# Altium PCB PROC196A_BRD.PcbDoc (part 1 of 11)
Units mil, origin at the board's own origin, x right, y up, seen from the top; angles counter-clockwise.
Board outline 3346.45 x 4921.26 mil, 8 copper layers (Top Layer, GND1, SIG1, PWR1, PWR2, SIG2, GND2, Bottom Layer), stack 54.534 mil thick; 736 components, 498 nets, 3030 pads, 1279 vias.
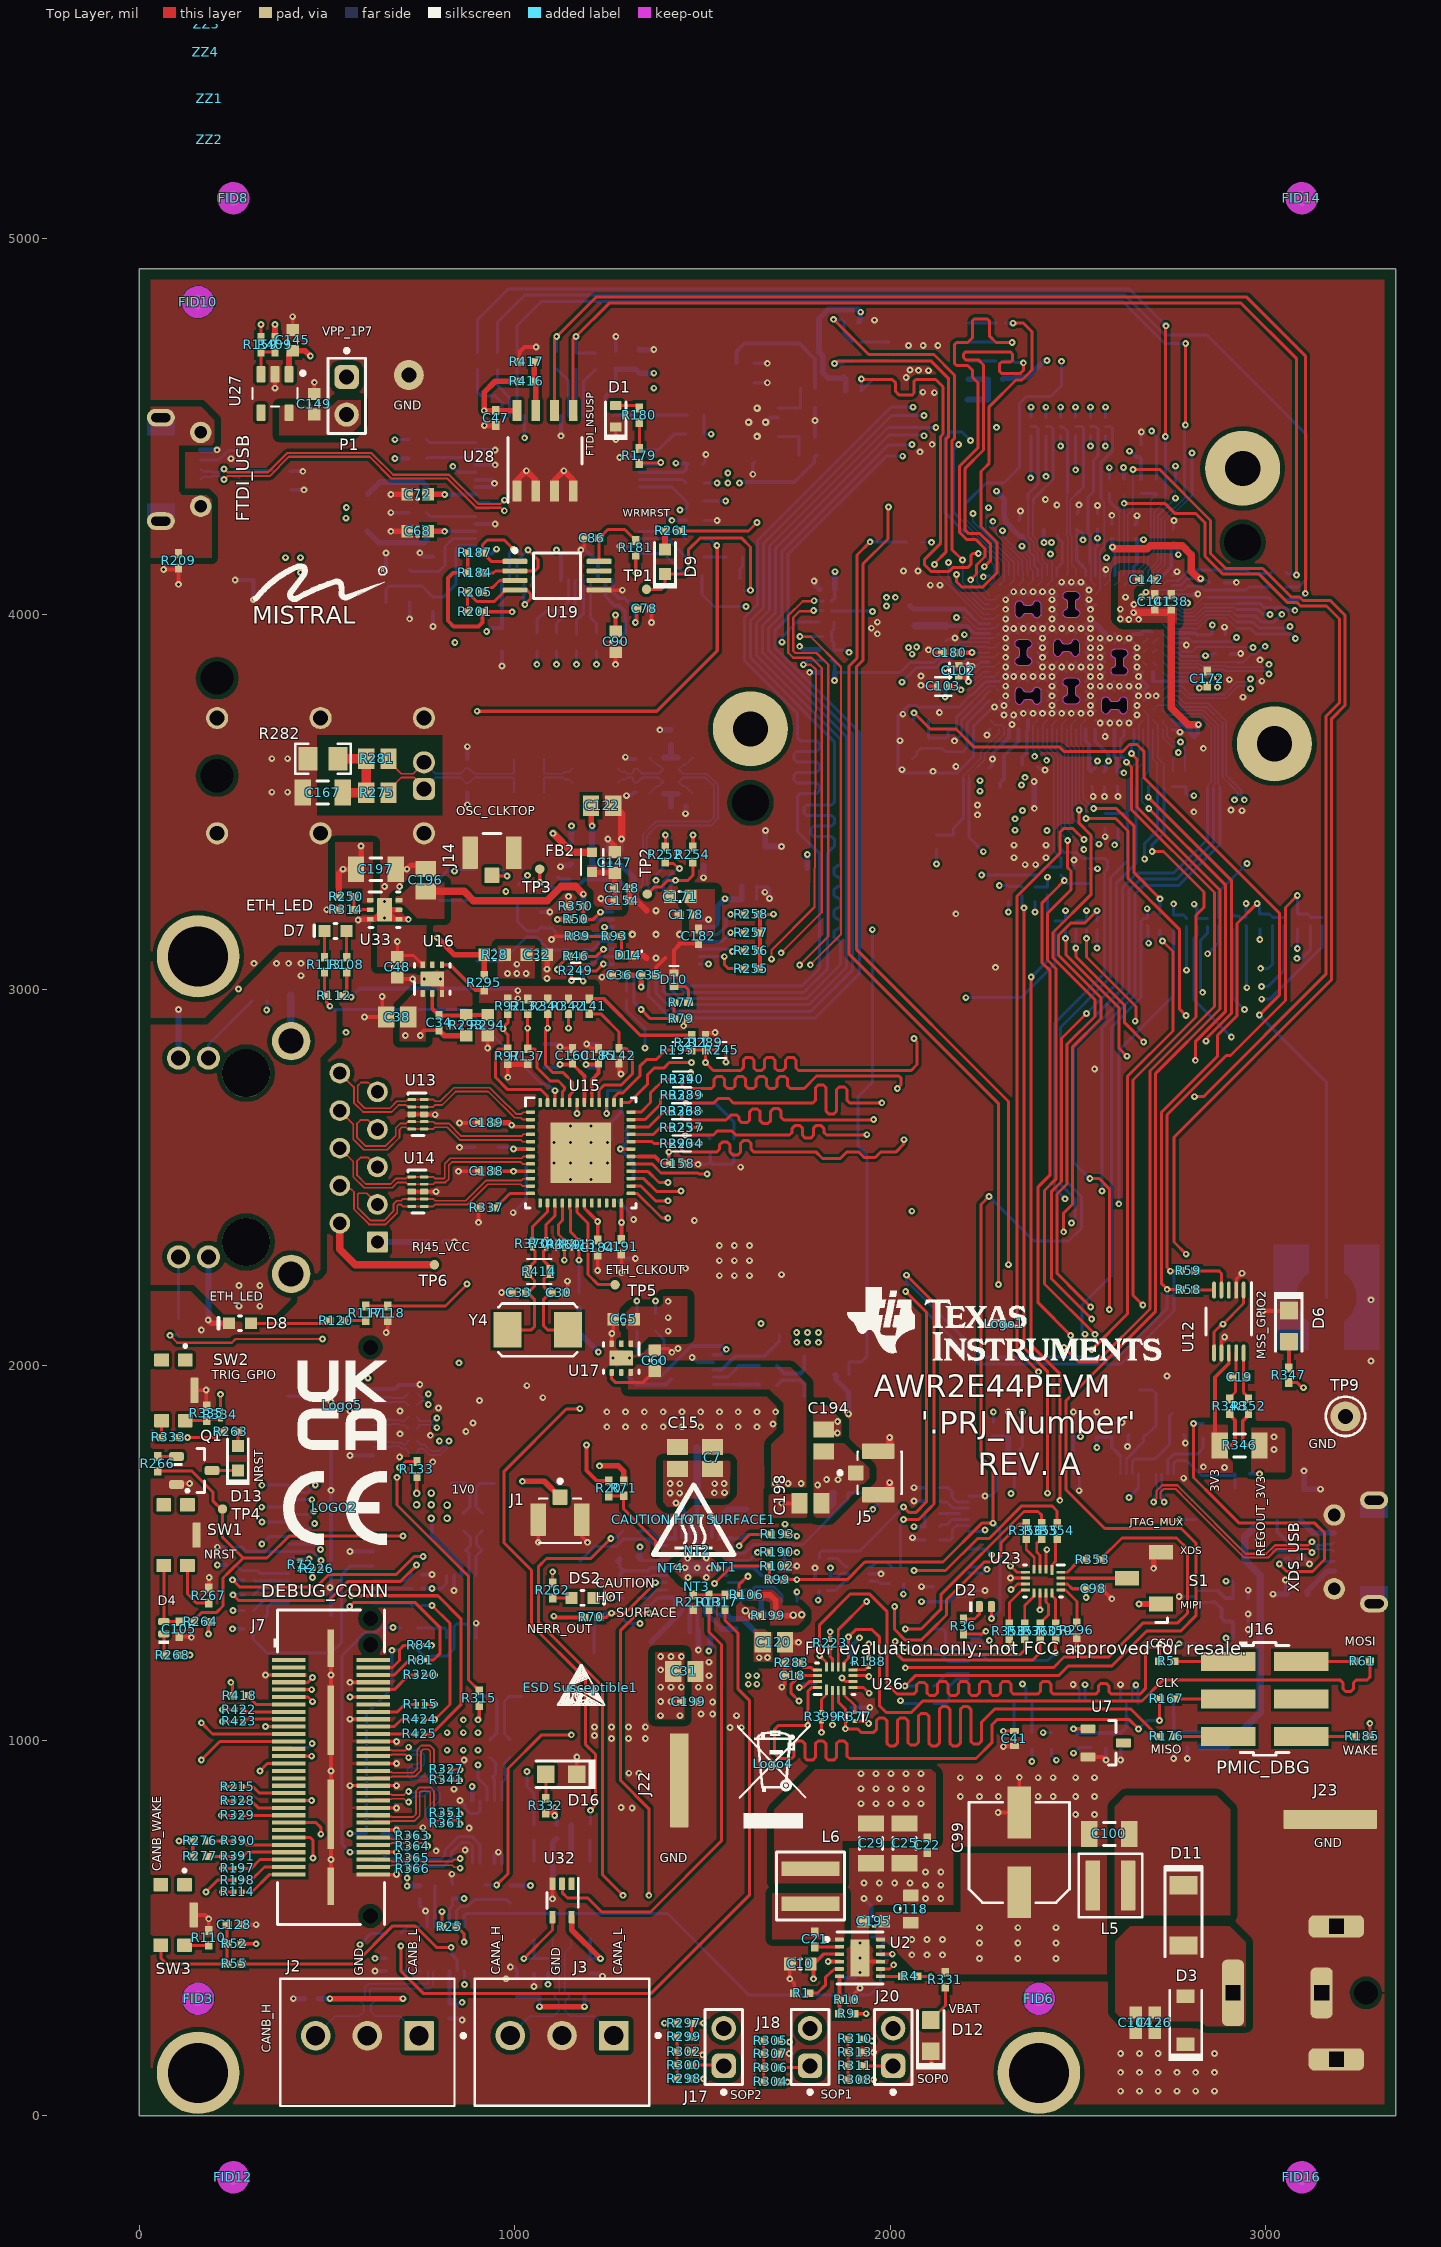
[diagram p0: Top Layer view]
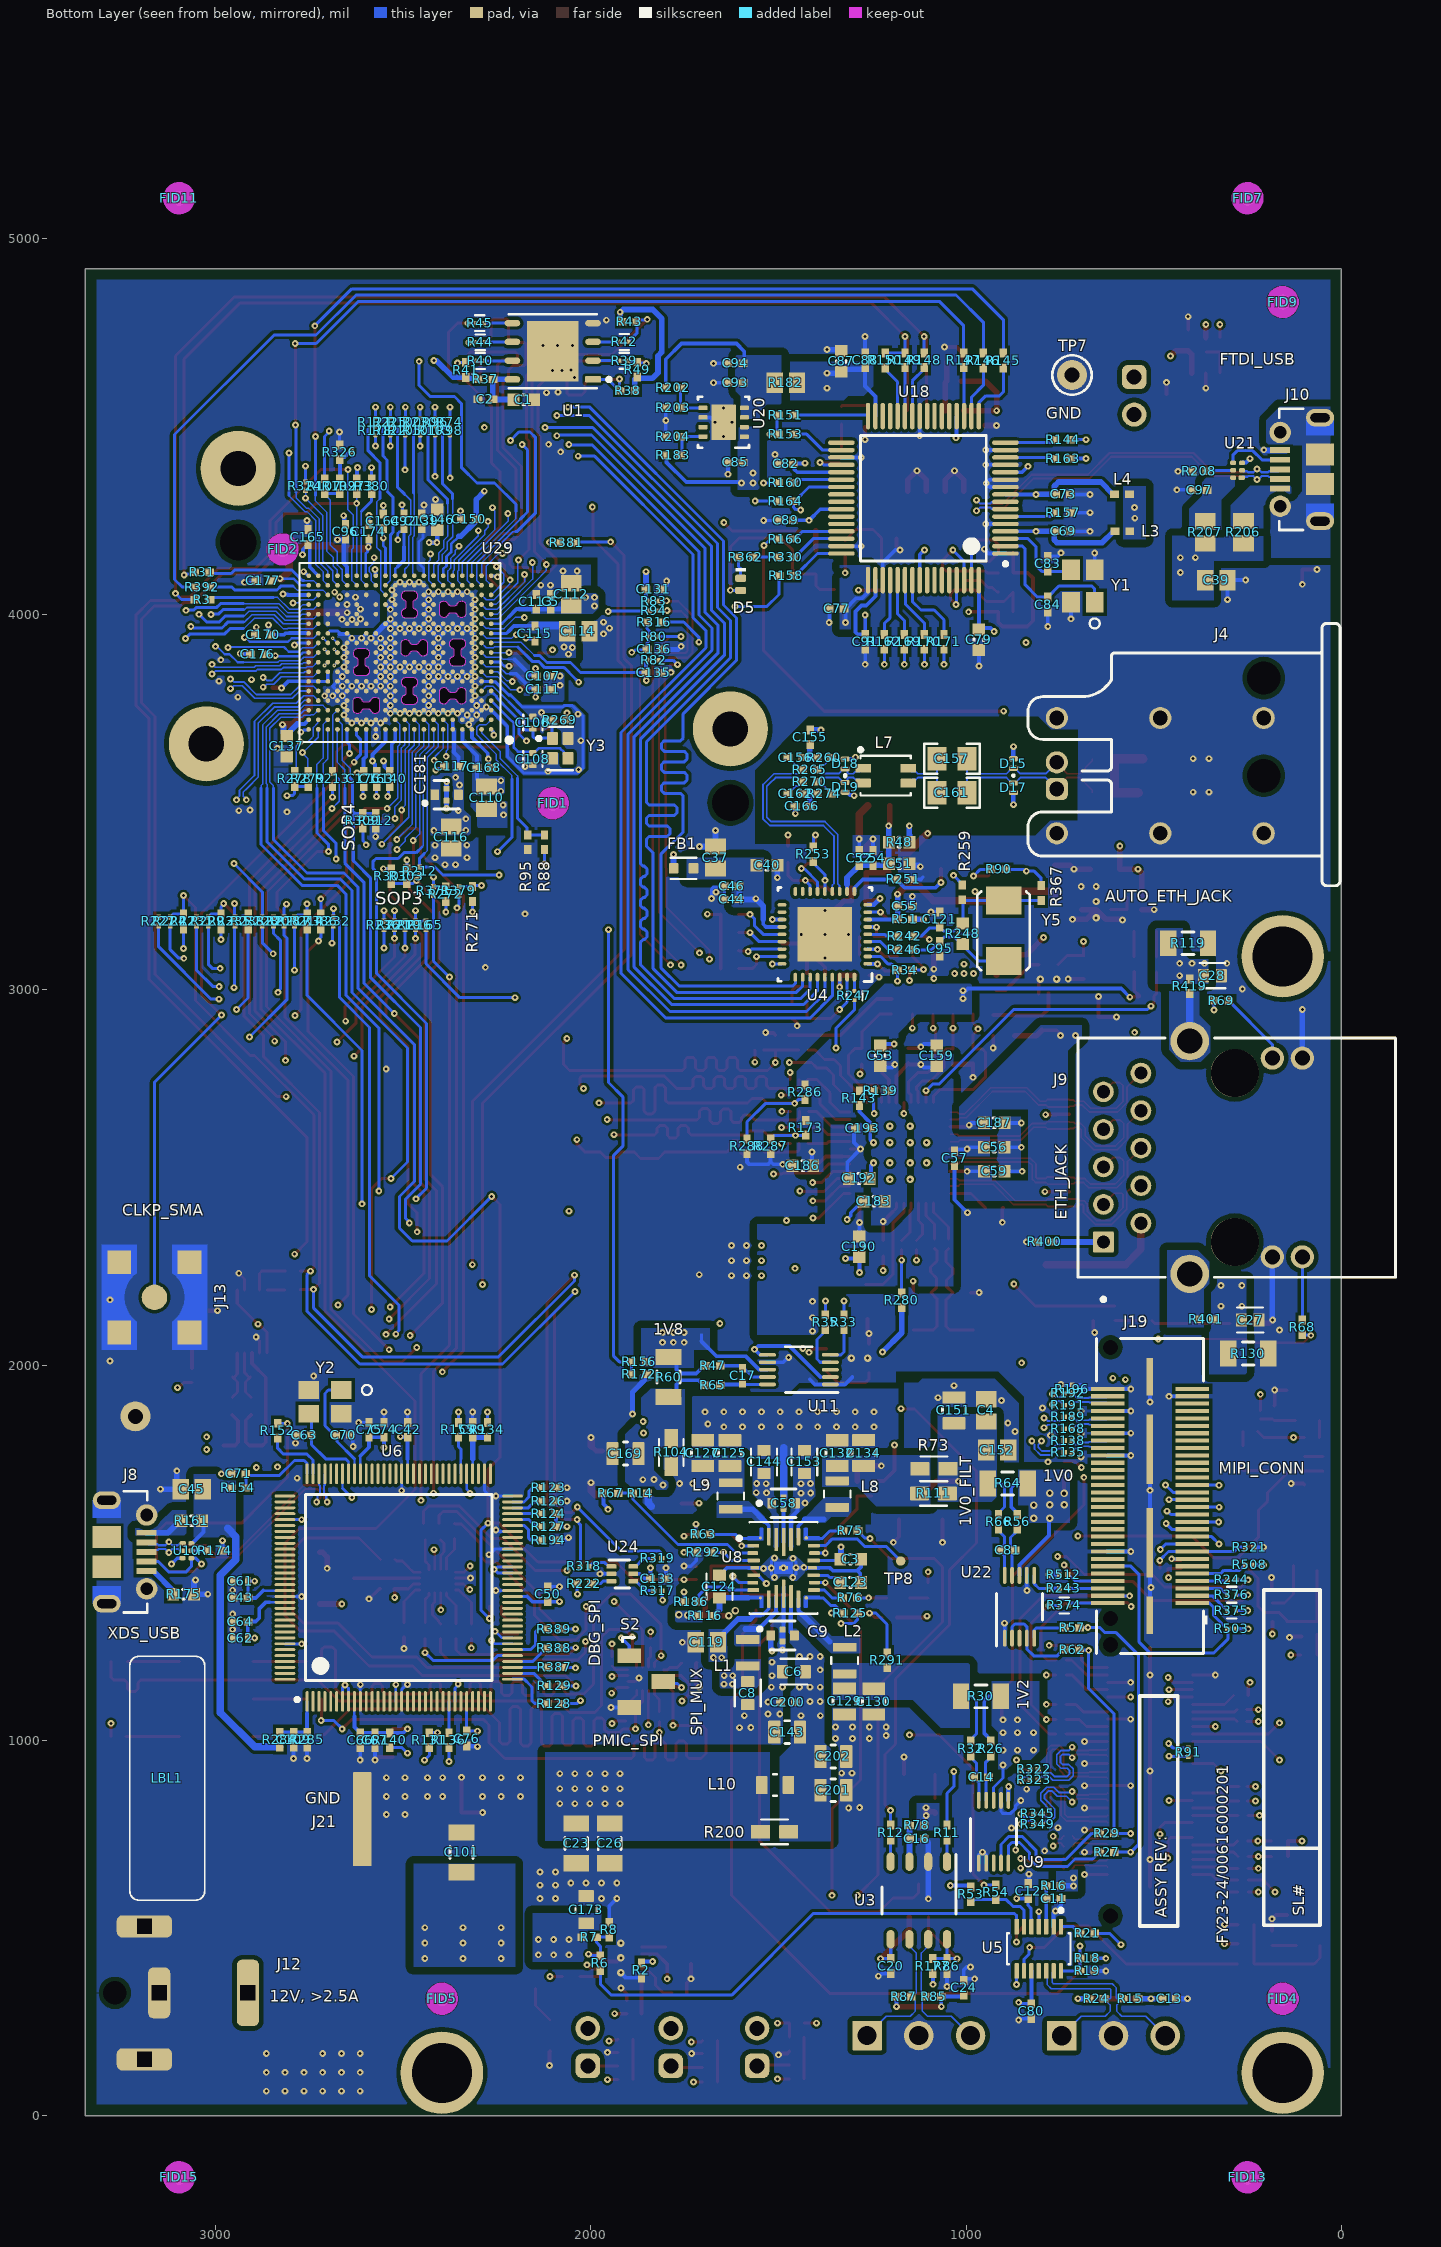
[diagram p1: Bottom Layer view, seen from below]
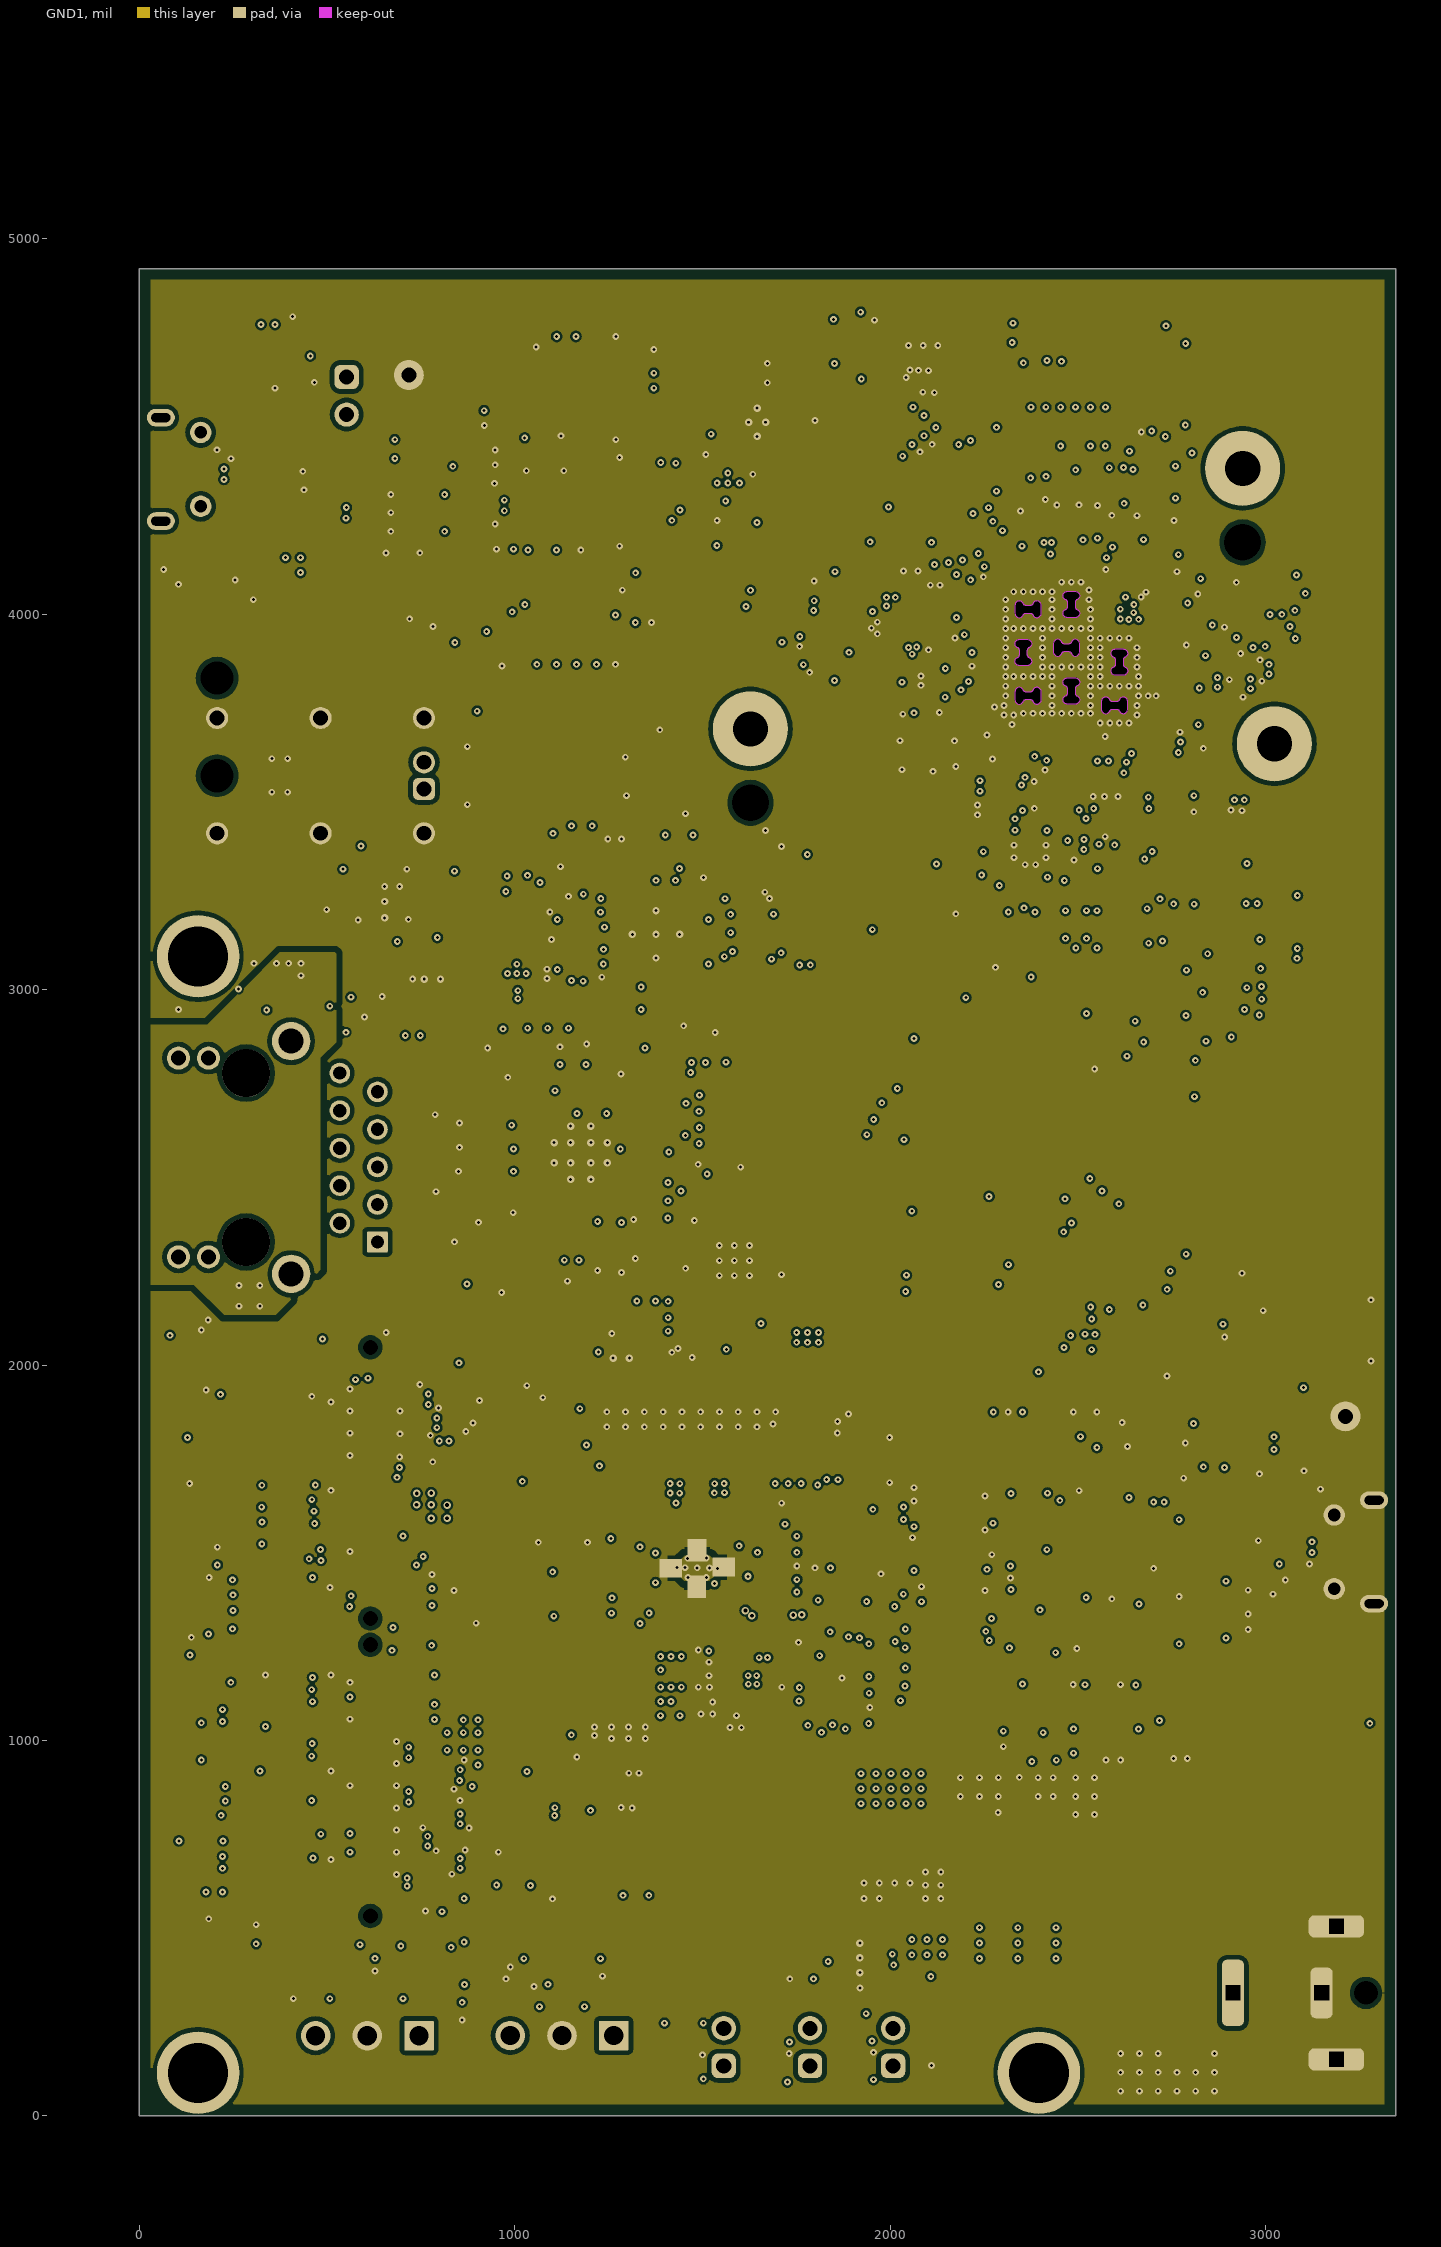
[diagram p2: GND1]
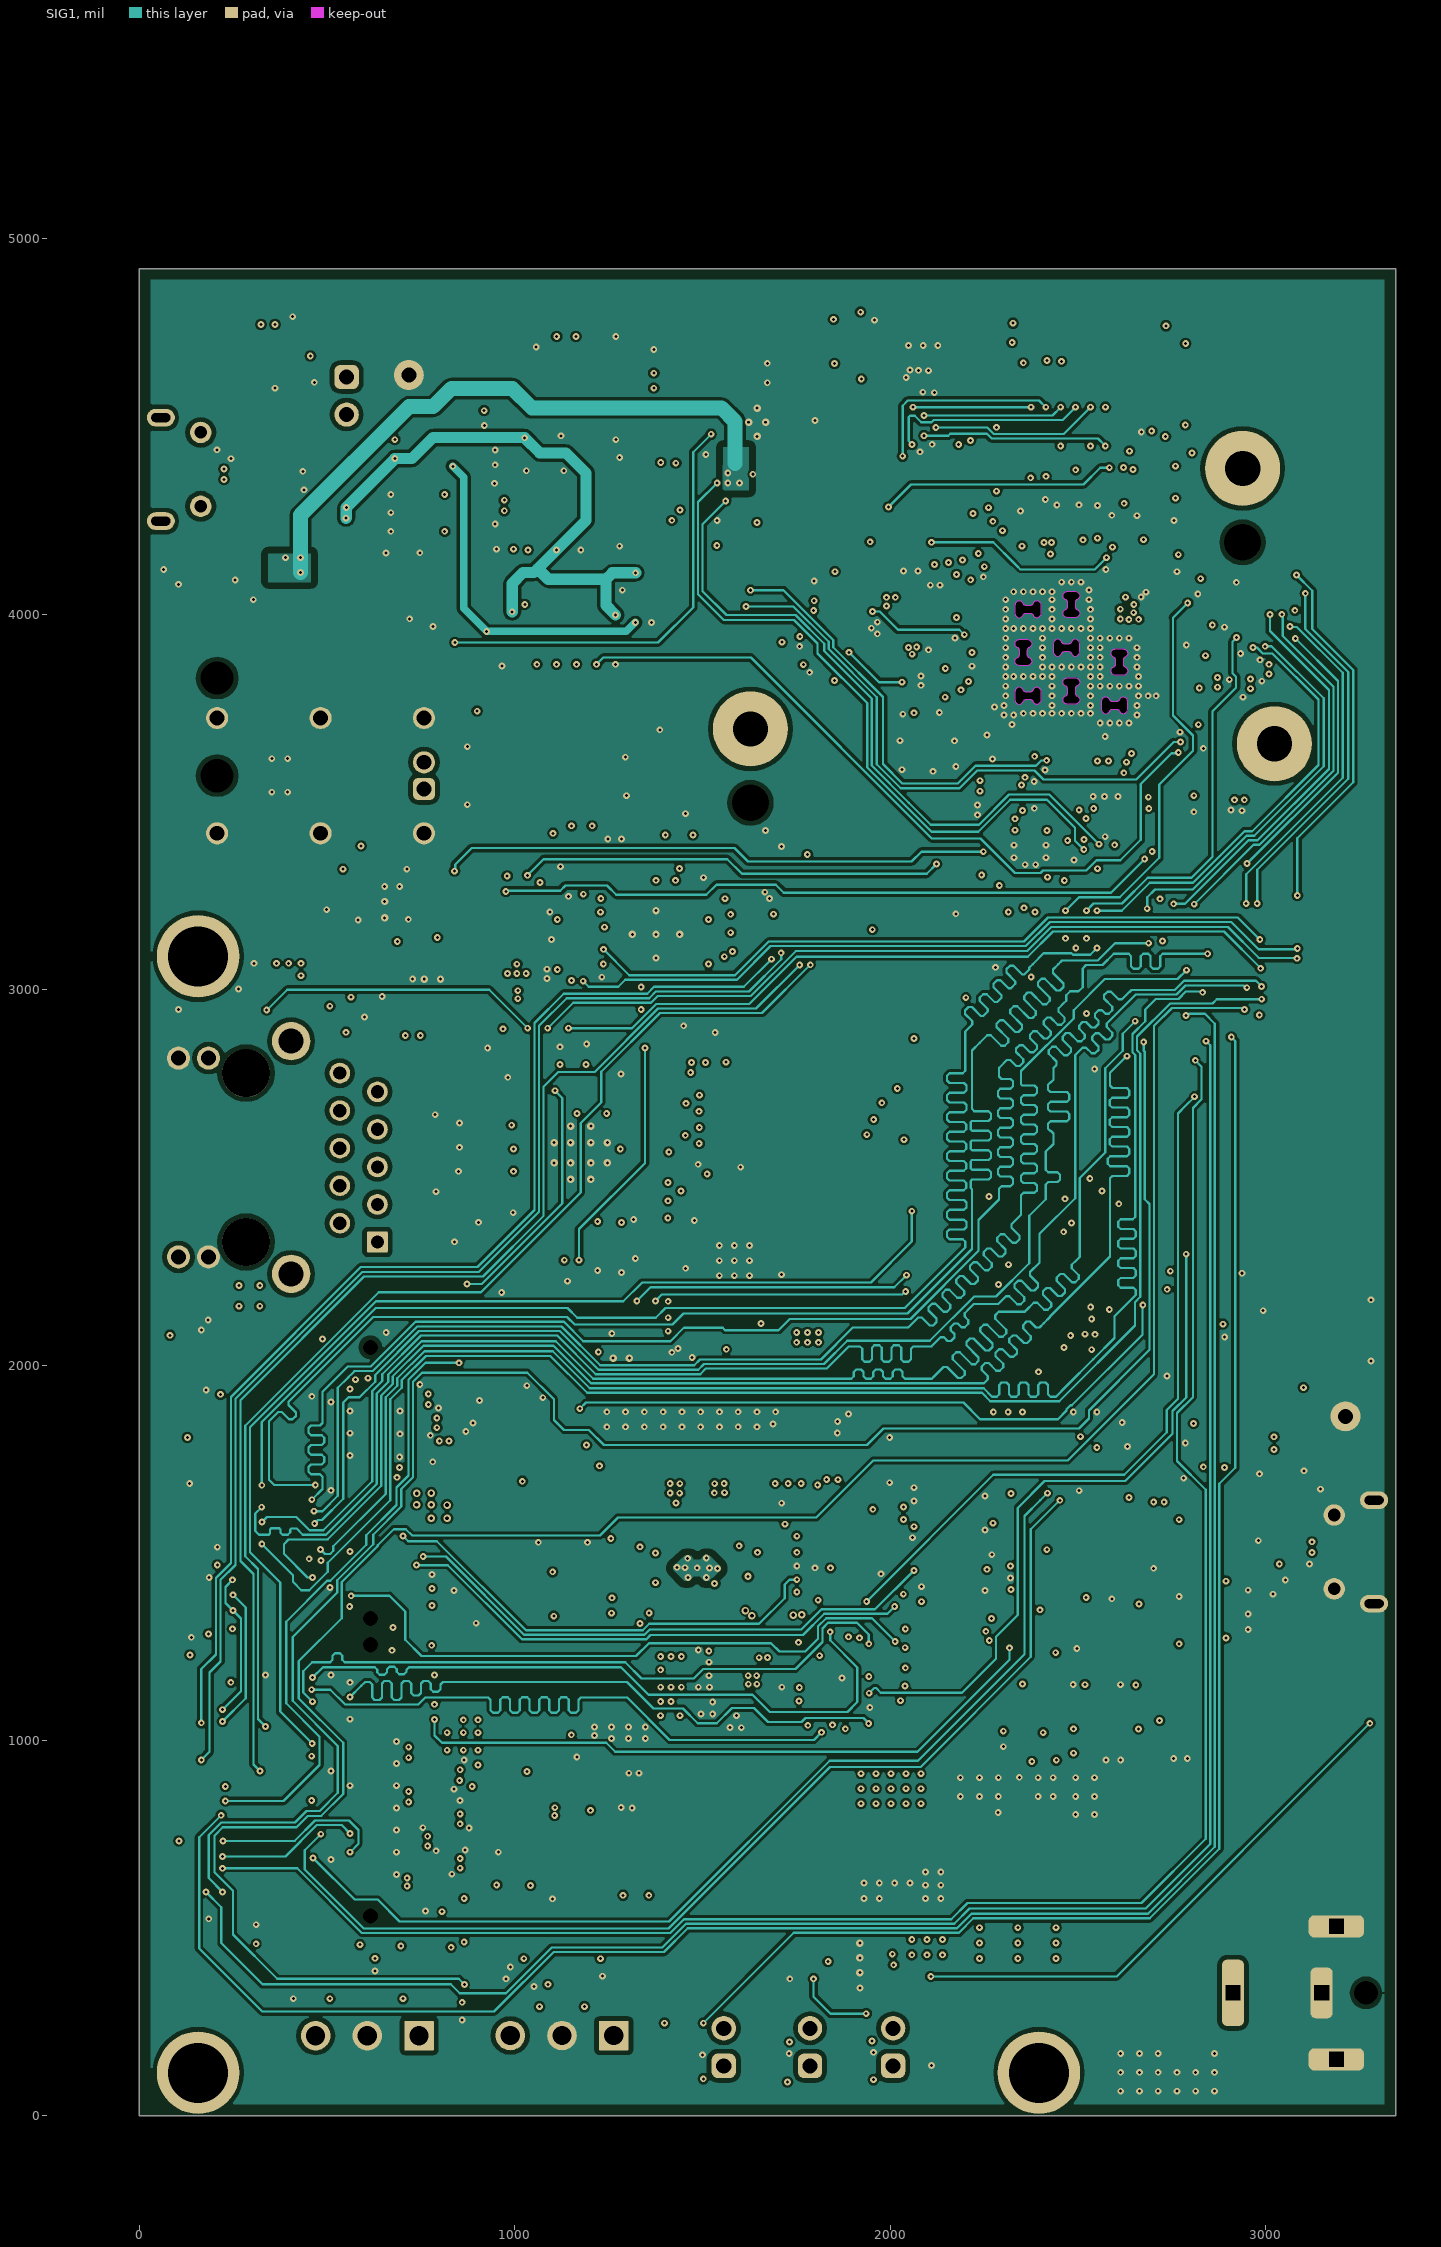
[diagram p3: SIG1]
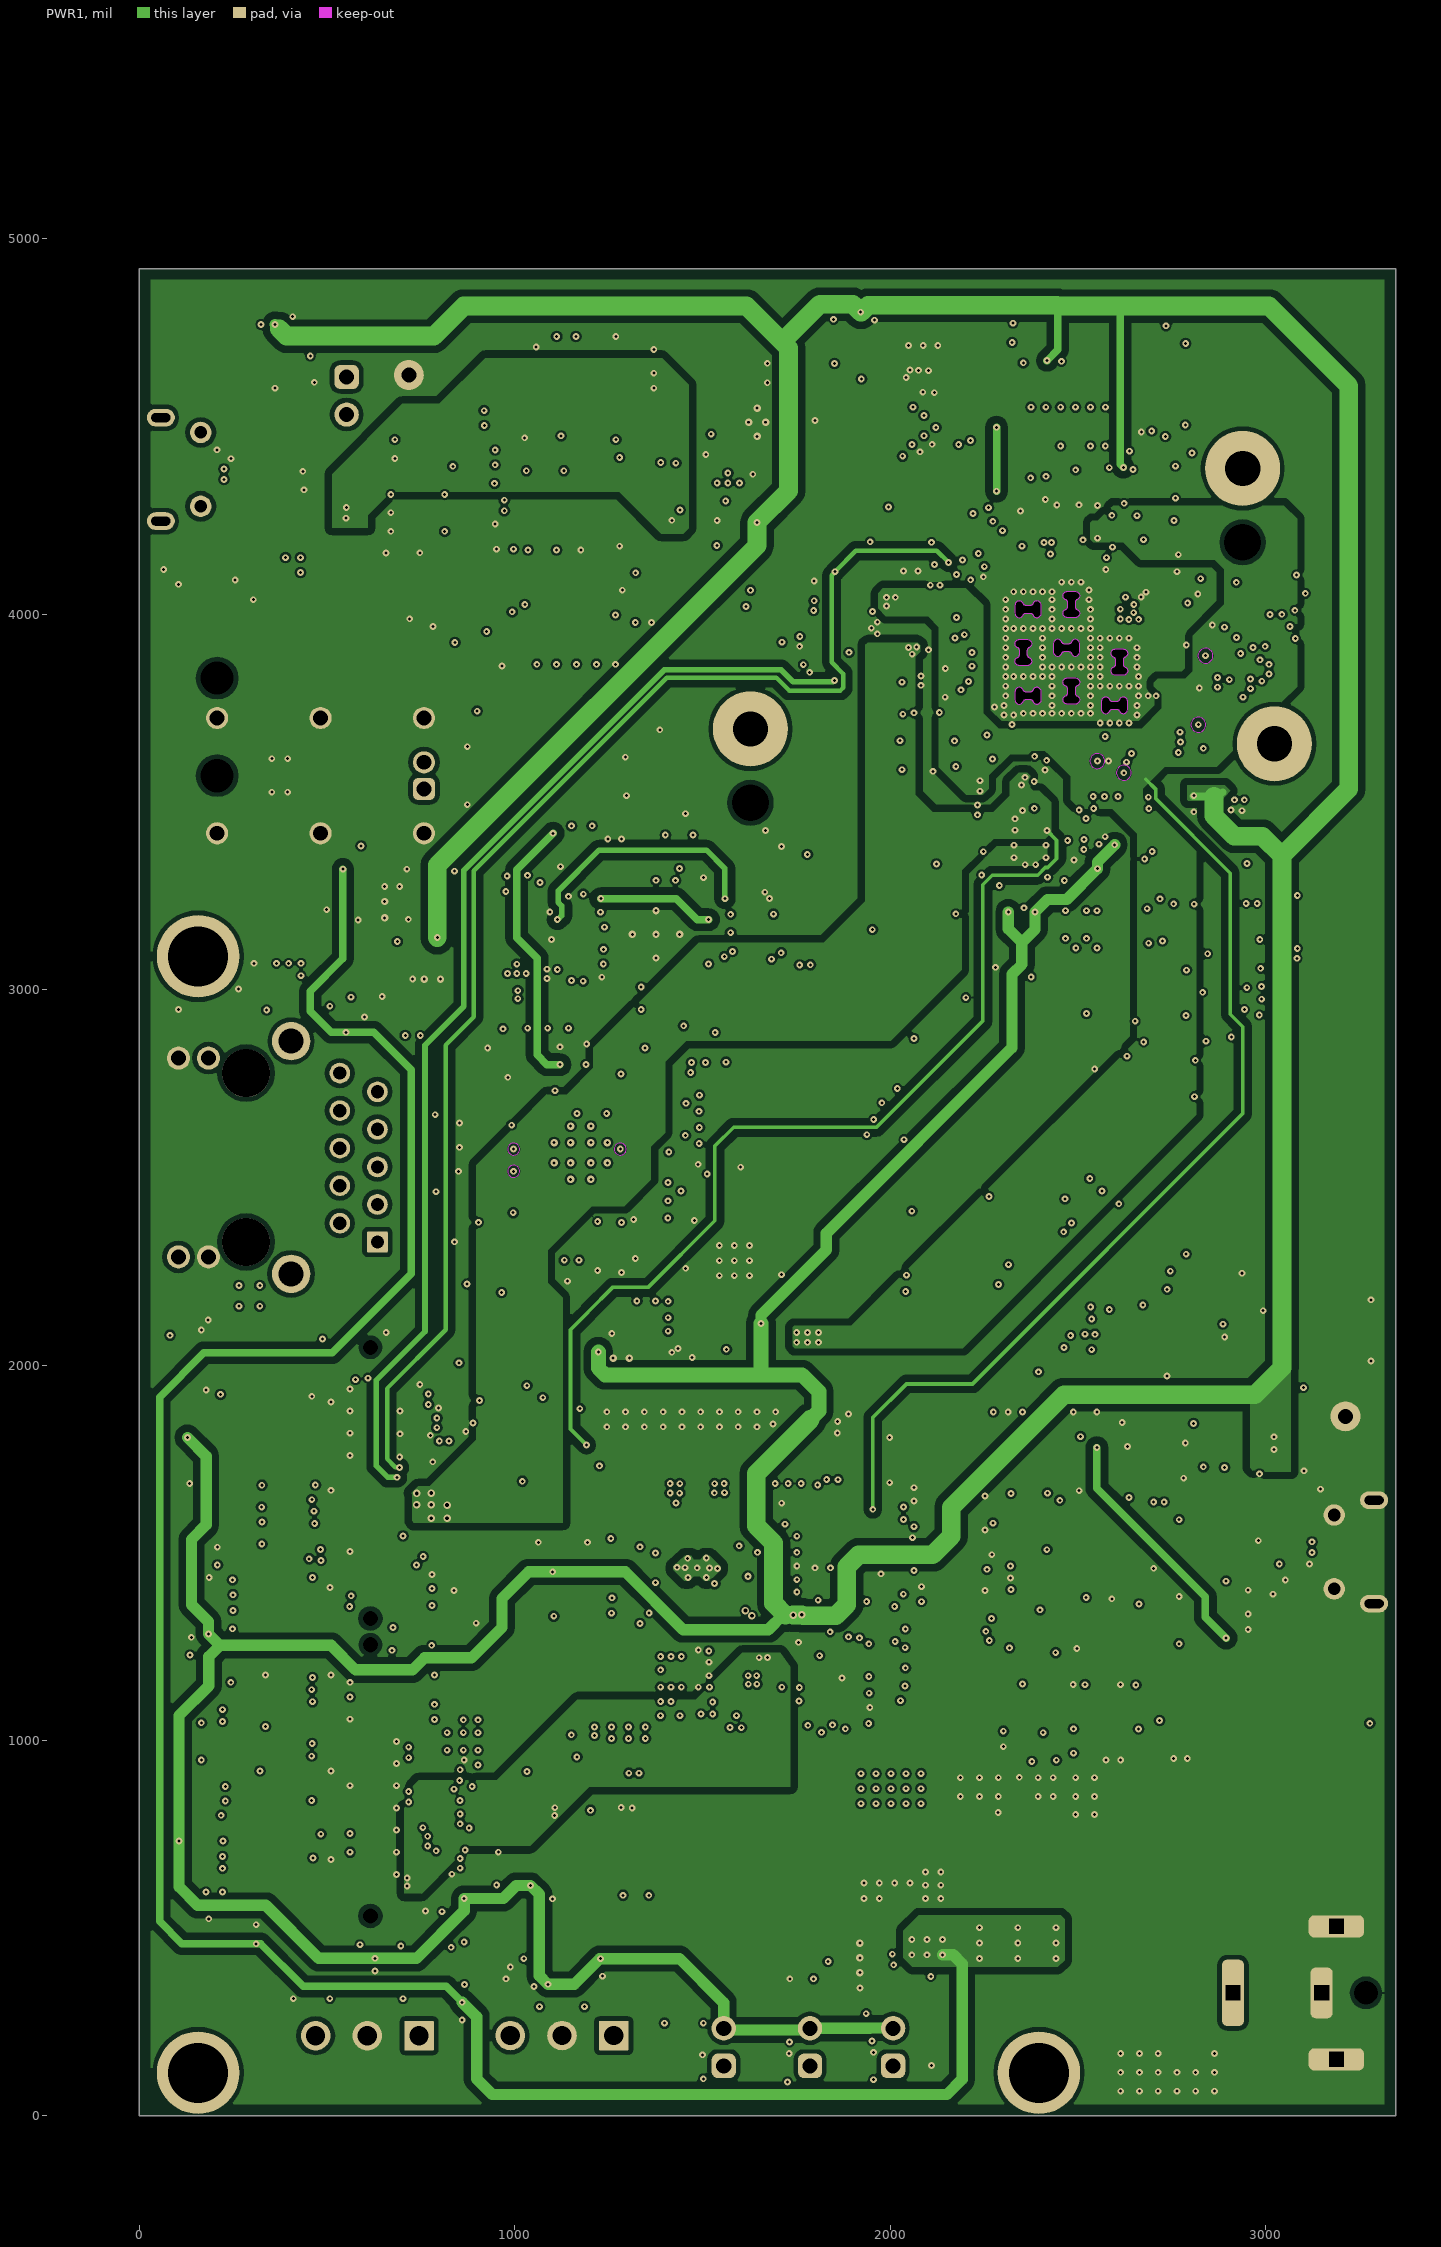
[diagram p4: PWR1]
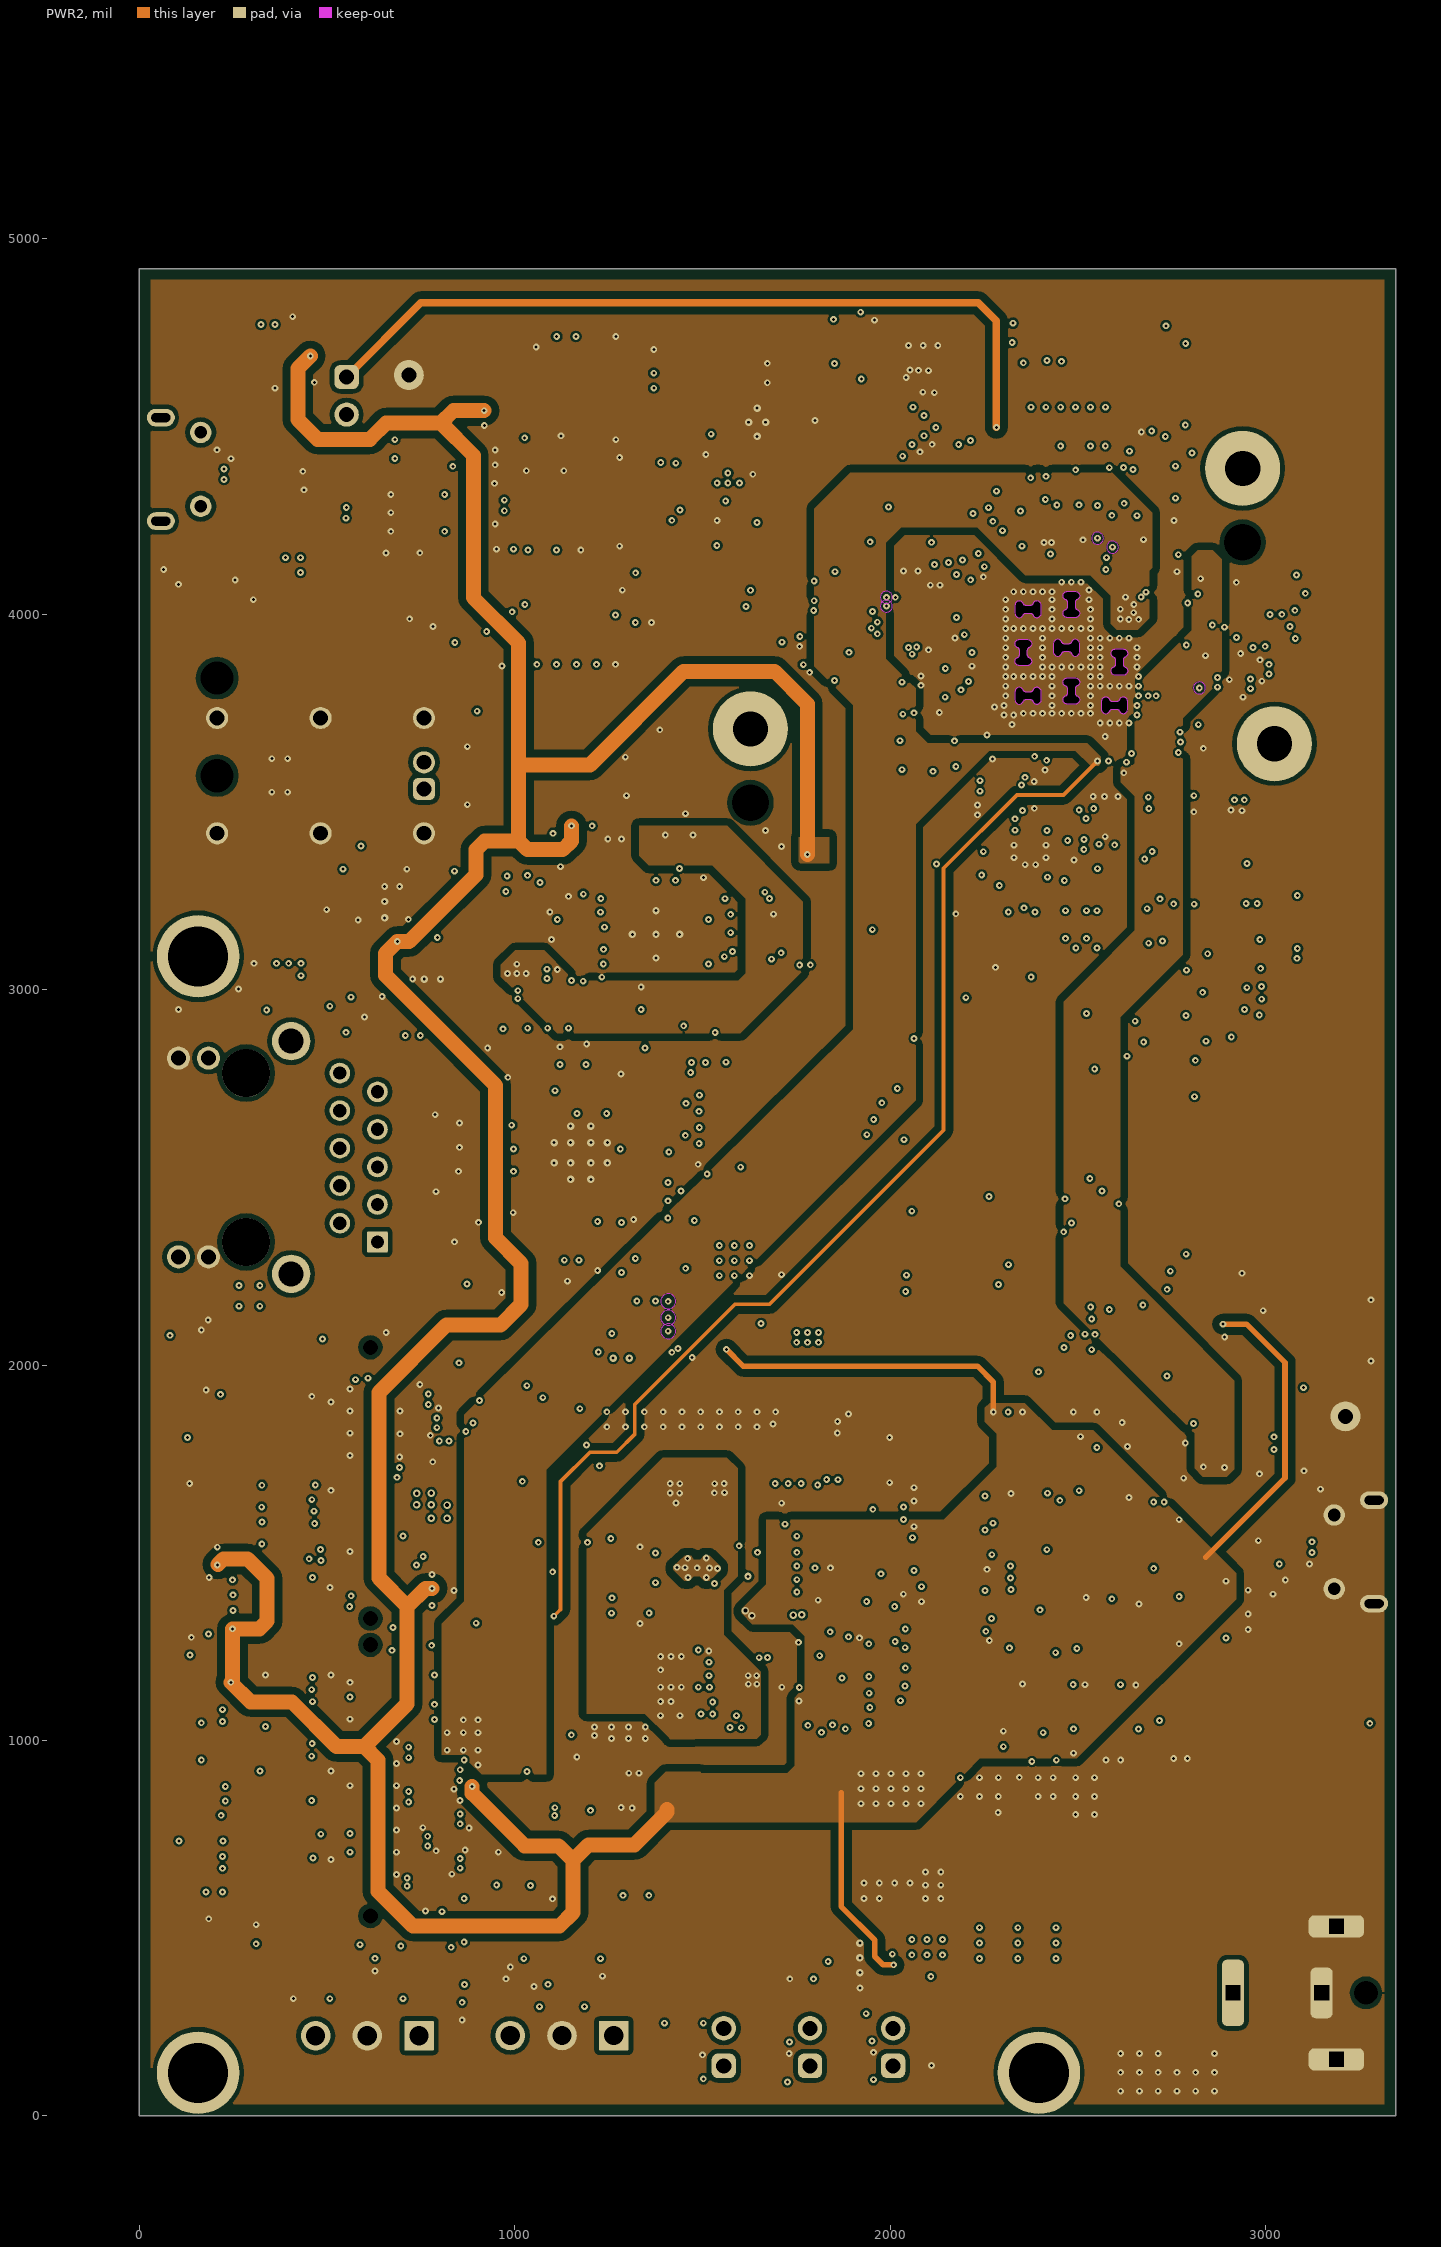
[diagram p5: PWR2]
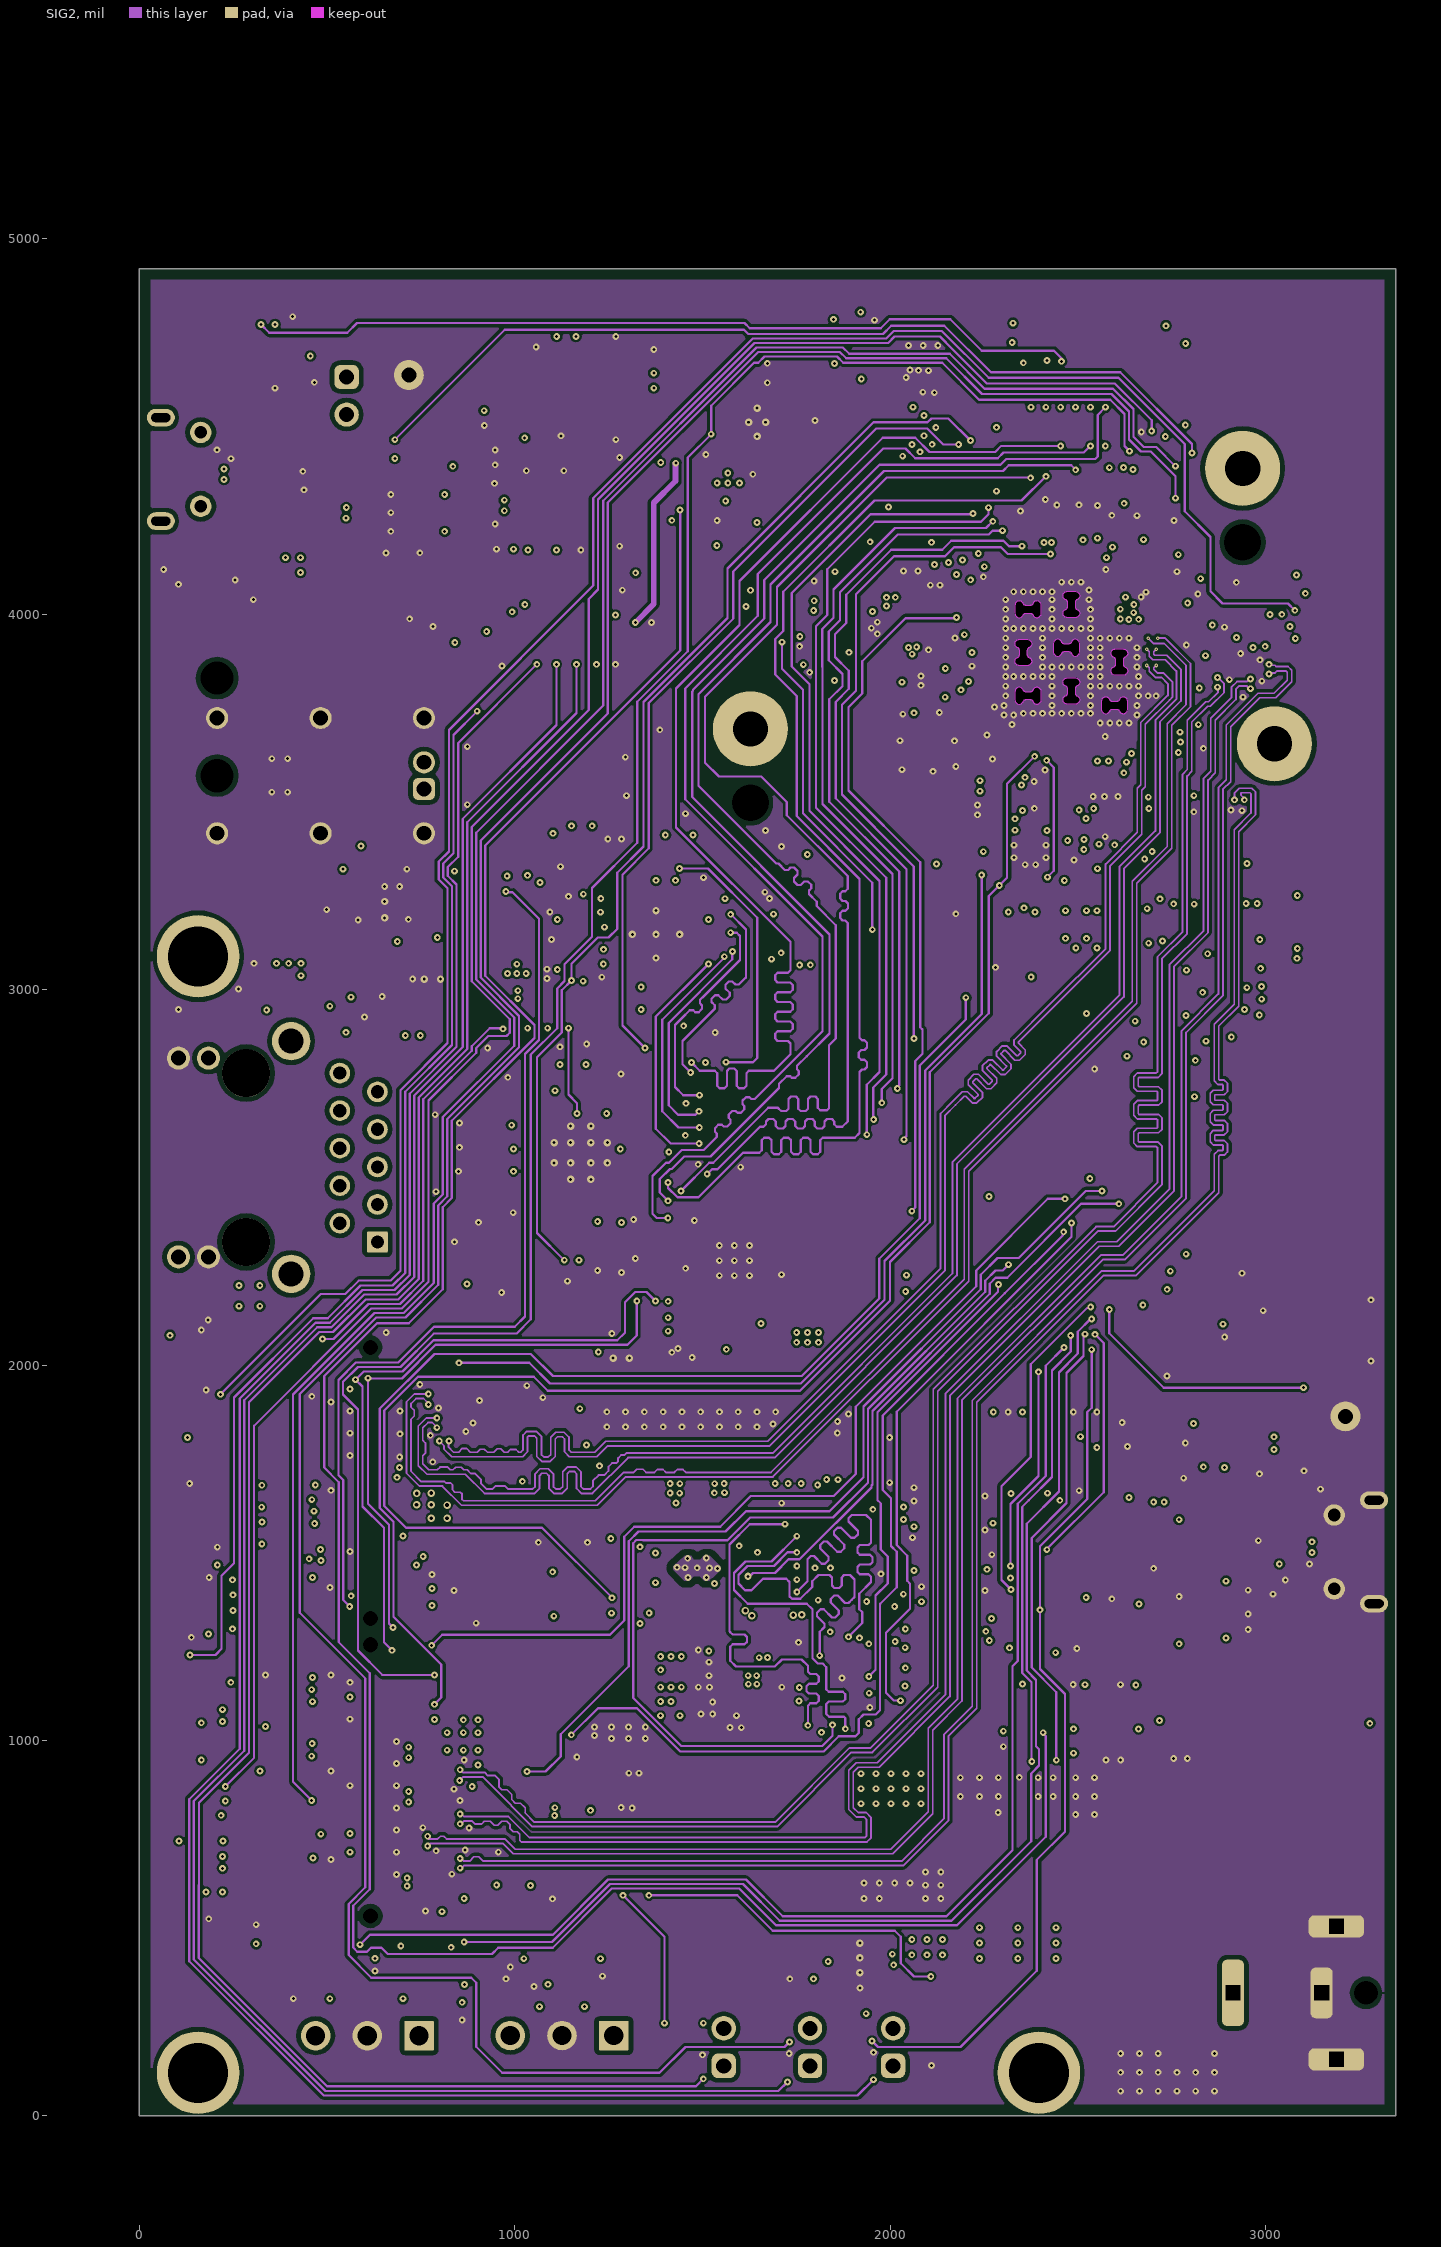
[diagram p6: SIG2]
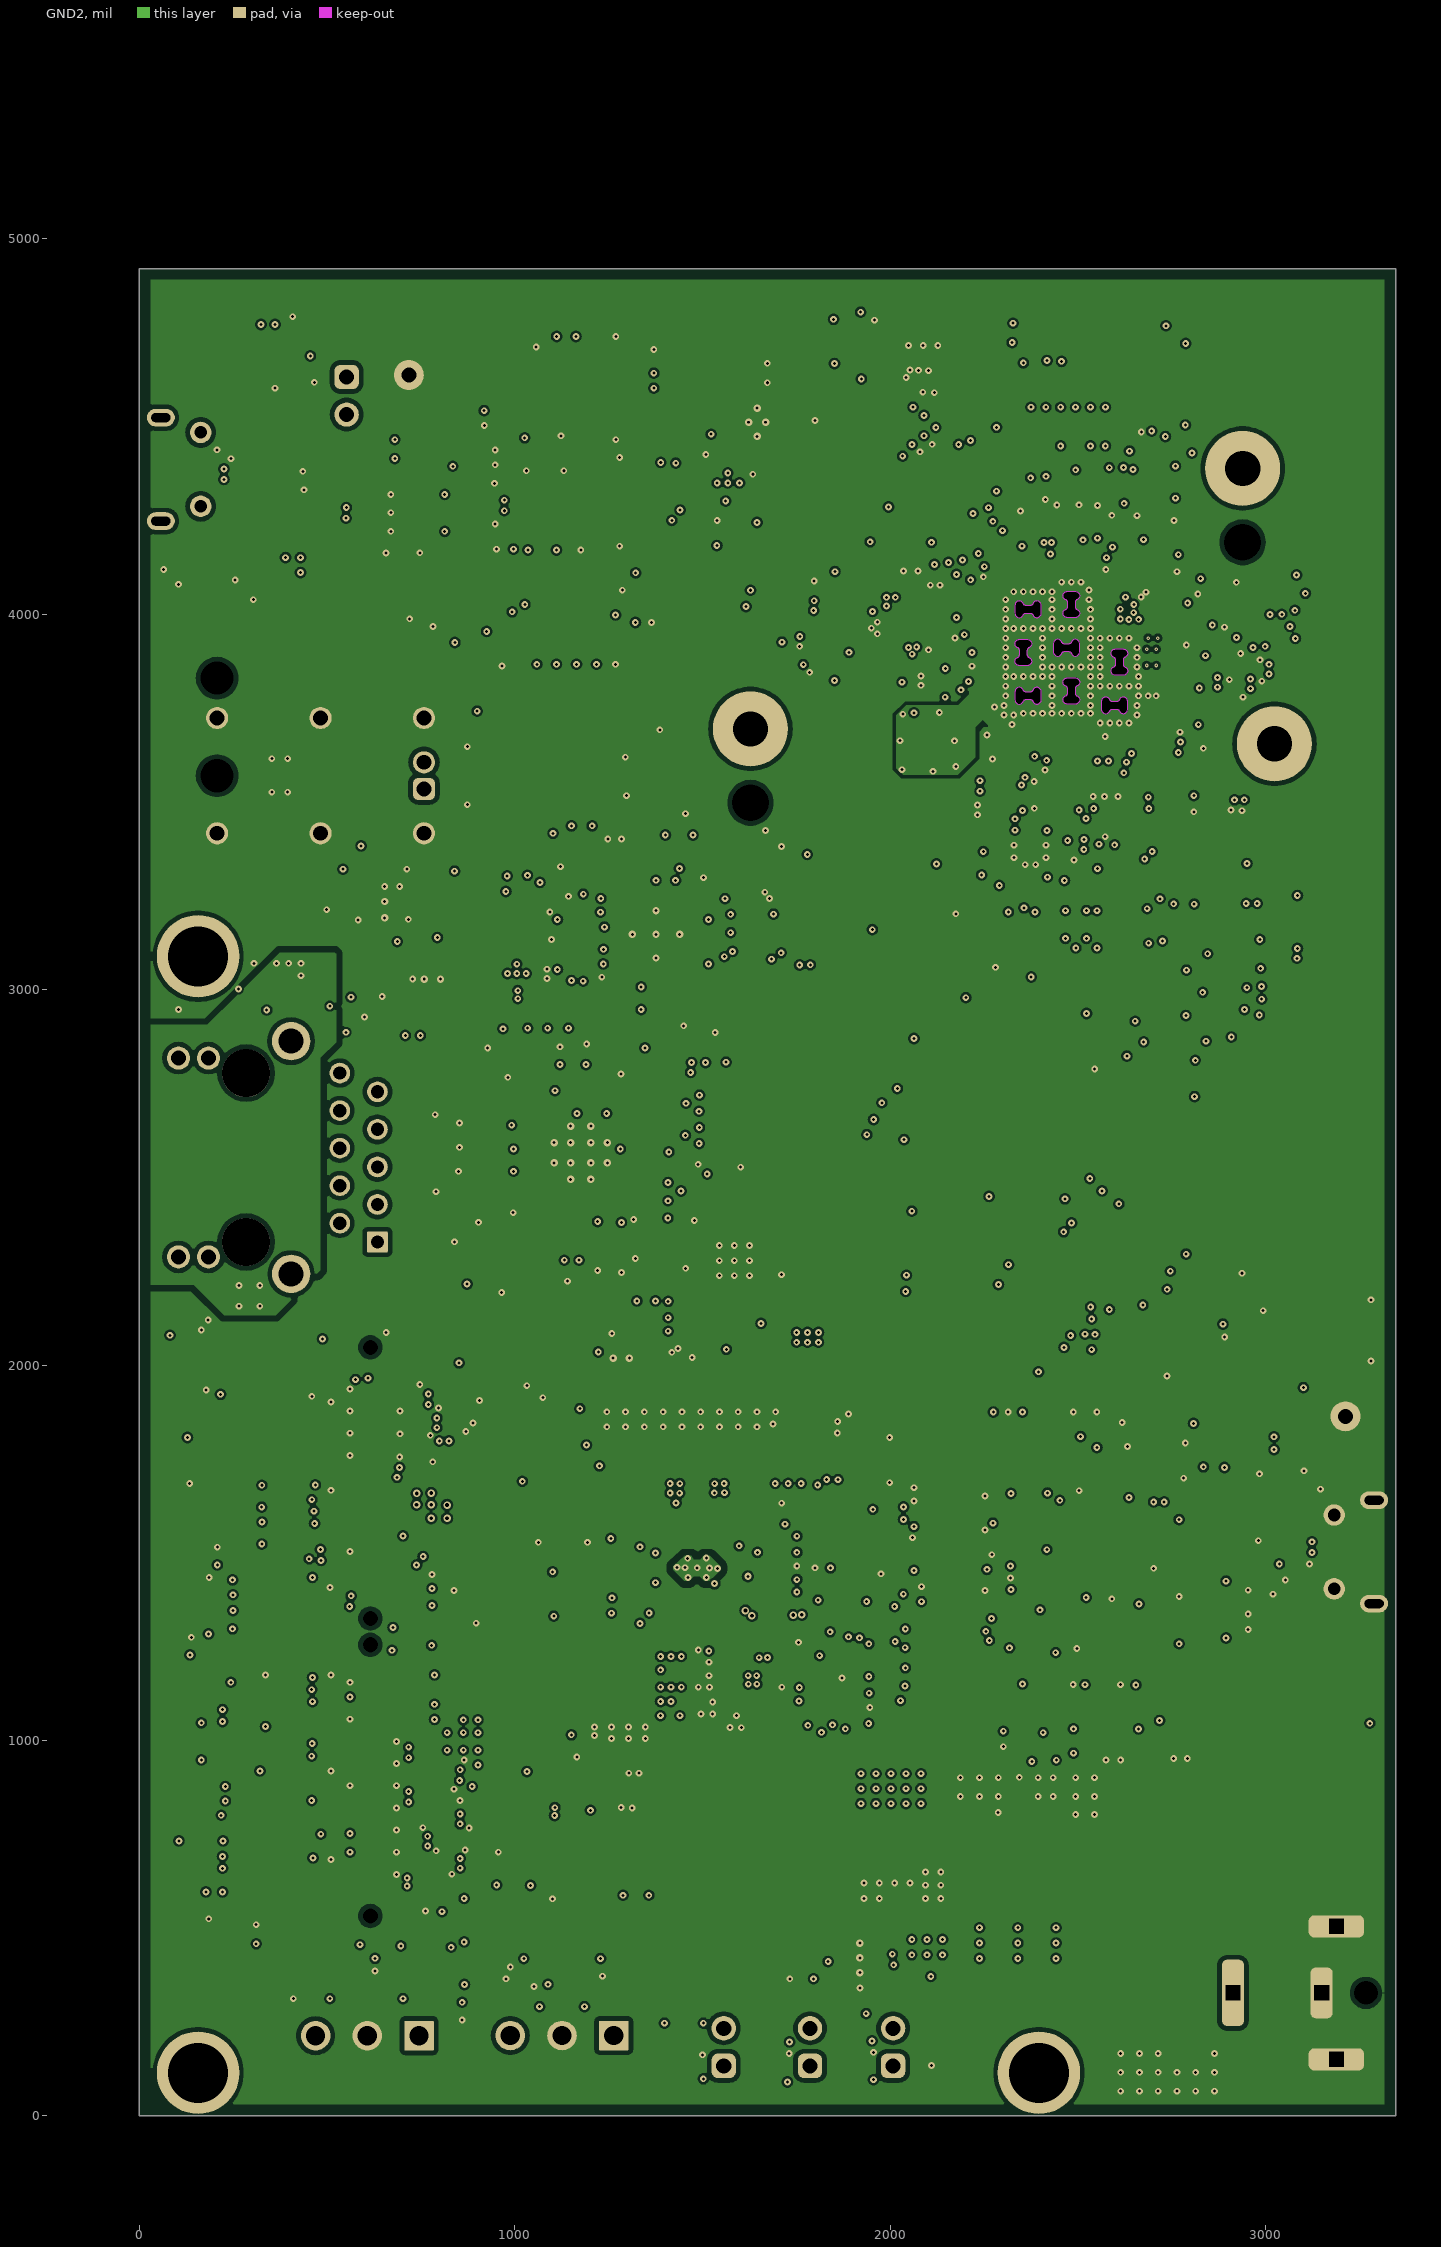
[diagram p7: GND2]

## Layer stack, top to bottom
Top Solder: solder mask 1, Solder Resist, Dk 3.5
Top Layer: signal copper 1.85
Dielectric 1: prepreg 4.396, FR-4 High Tg, Dk 3.54
GND1: signal copper 1.26
Dielectric 2: core 5, FR-4 High Tg, Dk 3.88
SIG1: signal copper 0.689
Dielectric 3: prepreg 10.312, FR-4 High Tg, Dk 3.86
PWR1: signal copper 1.26
Dielectric 4: prepreg 5, FR-4 High Tg, Dk 3.88
PWR2: signal copper 1.26
Dielectric 5: prepreg 10.312, FR-4 High Tg, Dk 3.86
SIG2: signal copper 0.689
Dielectric 6: core 5, FR-4 High Tg, Dk 3.88
GND2: signal copper 1.26
Dielectric 7: prepreg 4.396, FR-4 High Tg, Dk 3.54
Bottom Layer: signal copper 1.85
Bottom Solder: solder mask 1, Solder Resist, Dk 3.5

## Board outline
0,0 0,4921.25 3346.45,4921.26 3346.45,0
cut-out: 2336.08,3994.62 ccw(c2344.43,4002.97) 2344.24,3991.16 ccw(c2344.04,4002.97) 2352.39,3994.62 ccw(c2344.04,4002.97) 2355.01,3998.6 cw(c2362.33,3995.69) 2357.91,4002.21 cw(c2362.33,3995.69) 2362.33,4003.56 2373,4003.56 cw(c2373,3995.69) 2377.42,4002.21 cw(c2373,3995.69) 2380.31,3998.6 ccw(c2391.28,4002.97) 2382.93,3994.62 ccw(c2391.29,4002.97) 2391.09,3991.16 ccw(c2390.89,4002.97) 2399.24,3994.62 ccw(c2390.89,4002.97) 2402.7,4002.97 2402.7,4023.84 ccw(c2390.89,4023.84) 2399.24,4032.19 ccw(c2390.89,4023.84) 2391.09,4035.65 ccw(c2391.28,4023.84) 2382.93,4032.19 ccw(c2391.29,4023.84) 2380.31,4028.21 cw(c2373,4031.12) 2377.42,4024.6 cw(c2373,4031.12) 2373,4023.25 2362.33,4023.25 cw(c2362.33,4031.12) 2357.91,4024.6 cw(c2362.33,4031.12) 2355.01,4028.21 ccw(c2344.04,4023.84) 2352.39,4032.19 ccw(c2344.04,4023.84) 2344.24,4035.65 ccw(c2344.43,4023.84) 2336.08,4032.19 ccw(c2344.43,4023.84) 2332.62,4023.84 2332.62,4002.97 ccw(c2344.43,4002.97) 2332.64,4002.29 ccw(c2344.43,4002.97)
cut-out: 2336.08,3866.67 cw(c2344.43,3875.02) 2332.63,3874.82 cw(c2344.43,3874.63) 2336.08,3882.98 cw(c2344.43,3874.63) 2340.06,3885.6 ccw(c2337.15,3892.91) 2343.67,3888.49 ccw(c2337.15,3892.91) 2345.03,3892.91 2345.03,3903.58 ccw(c2337.15,3903.58) 2343.67,3908 ccw(c2337.15,3903.58) 2340.06,3910.9 cw(c2344.43,3921.87) 2336.08,3913.52 cw(c2344.43,3921.87) 2332.63,3921.67 cw(c2344.43,3921.48) 2336.08,3929.83 cw(c2344.43,3921.48) 2344.43,3933.29 2365.3,3933.29 cw(c2365.3,3921.48) 2373.65,3929.83 cw(c2365.3,3921.48) 2377.11,3921.67 cw(c2365.3,3921.87) 2373.65,3913.52 cw(c2365.3,3921.87) 2369.67,3910.9 ccw(c2372.58,3903.58) 2366.07,3908 ccw(c2372.58,3903.58) 2364.71,3903.58 2364.71,3892.91 ccw(c2372.58,3892.91) 2366.07,3888.49 ccw(c2372.58,3892.91) 2369.67,3885.6 cw(c2365.3,3874.63) 2373.65,3882.98 cw(c2365.3,3874.63) 2377.11,3874.82 cw(c2365.3,3875.02) 2373.65,3866.67 cw(c2365.3,3875.02) 2365.98,3863.23 cw(c2365.3,3875.02) 2365.3,3863.21 2344.43,3863.21 cw(c2344.43,3875.02)
cut-out: 2438.45,3892.26 ccw(c2446.8,3900.61) 2446.6,3888.8 ccw(c2446.4,3900.61) 2454.75,3892.26 ccw(c2446.4,3900.61) 2457.38,3896.24 cw(c2464.69,3893.33) 2460.27,3899.84 cw(c2464.69,3893.33) 2464.69,3901.2 2475.36,3901.2 cw(c2475.36,3893.33) 2479.78,3899.84 cw(c2475.36,3893.33) 2482.67,3896.24 ccw(c2493.65,3900.61) 2485.3,3892.26 ccw(c2493.65,3900.61) 2493.45,3888.8 ccw(c2493.25,3900.61) 2501.61,3892.26 ccw(c2493.25,3900.61) 2505.06,3900.61 2505.06,3921.48 ccw(c2493.25,3921.48) 2501.61,3929.83 ccw(c2493.25,3921.48) 2493.45,3933.28 ccw(c2493.65,3921.48) 2485.3,3929.83 ccw(c2493.65,3921.48) 2482.67,3925.85 cw(c2475.36,3928.76) 2479.78,3922.24 cw(c2475.36,3928.76) 2475.36,3920.89 2464.69,3920.89 cw(c2464.69,3928.76) 2460.27,3922.24 cw(c2464.69,3928.76) 2457.38,3925.85 ccw(c2446.41,3921.48) 2454.76,3929.83 ccw(c2446.4,3921.48) 2446.6,3933.28 ccw(c2446.8,3921.48) 2438.45,3929.83 ccw(c2446.8,3921.48) 2434.99,3921.48 2434.99,3900.61 ccw(c2446.8,3900.61) 2435.01,3899.93 ccw(c2446.8,3900.61)
cut-out: 2464.04,3994.62 cw(c2472.39,4002.97) 2460.58,4002.77 cw(c2472.39,4002.58) 2464.04,4010.93 cw(c2472.39,4002.58) 2468.02,4013.55 ccw(c2465.1,4020.87) 2471.62,4016.45 ccw(c2465.1,4020.87) 2472.98,4020.87 2472.98,4031.53 ccw(c2465.1,4031.53) 2471.62,4035.95 ccw(c2465.1,4031.54) 2468.02,4038.85 cw(c2472.39,4049.82) 2464.04,4041.47 cw(c2472.39,4049.82) 2460.58,4049.63 cw(c2472.39,4049.43) 2464.04,4057.78 cw(c2472.39,4049.43) 2472.39,4061.24 2493.25,4061.24 cw(c2493.25,4049.43) 2501.61,4057.78 cw(c2493.25,4049.43) 2505.06,4049.63 cw(c2493.25,4049.82) 2501.61,4041.47 cw(c2493.25,4049.82) 2497.62,4038.85 ccw(c2500.54,4031.53) 2494.02,4035.95 ccw(c2500.54,4031.53) 2492.66,4031.53 2492.66,4020.87 ccw(c2500.54,4020.87) 2494.02,4016.45 ccw(c2500.54,4020.87) 2497.62,4013.55 cw(c2493.26,4002.58) 2501.61,4010.93 cw(c2493.25,4002.58) 2505.06,4002.77 cw(c2493.25,4002.97) 2501.61,3994.62 cw(c2493.25,4002.97) 2493.94,3991.18 cw(c2493.25,4002.97) 2493.25,3991.16 2472.39,3991.16 cw(c2472.39,4002.97)
cut-out: 2591.99,3841.08 cw(c2600.34,3849.43) 2588.53,3849.23 cw(c2600.34,3849.03) 2591.99,3857.39 cw(c2600.34,3849.04) 2595.97,3860.01 ccw(c2593.06,3867.32) 2599.57,3862.9 ccw(c2593.06,3867.32) 2600.93,3867.32 2600.93,3877.99 ccw(c2593.06,3877.99) 2599.57,3882.41 ccw(c2593.06,3877.99) 2595.97,3885.31 cw(c2600.34,3896.28) 2591.99,3887.93 cw(c2600.34,3896.28) 2588.53,3896.08 cw(c2600.34,3895.89) 2591.99,3904.24 cw(c2600.34,3895.89) 2600.34,3907.7 2621.21,3907.7 cw(c2621.21,3895.89) 2629.56,3904.24 cw(c2621.21,3895.89) 2633.02,3896.08 cw(c2621.21,3896.28) 2629.56,3887.93 cw(c2621.21,3896.28) 2625.58,3885.31 ccw(c2628.49,3877.99) 2621.97,3882.41 ccw(c2628.49,3877.99) 2620.62,3877.99 2620.62,3867.32 ccw(c2628.49,3867.32) 2621.97,3862.9 ccw(c2628.49,3867.32) 2625.58,3860.01 cw(c2621.21,3849.04) 2629.56,3857.39 cw(c2621.21,3849.03) 2633.02,3849.23 cw(c2621.21,3849.43) 2629.56,3841.08 cw(c2621.21,3849.43) 2621.89,3837.64 cw(c2621.21,3849.43) 2621.21,3837.62 2600.34,3837.62 cw(c2600.34,3849.43)
cut-out: 2566.4,3738.71 ccw(c2574.75,3747.07) 2574.55,3735.26 ccw(c2574.36,3747.07) 2582.71,3738.71 ccw(c2574.36,3747.07) 2585.33,3742.7 cw(c2592.64,3739.78) 2588.22,3746.3 cw(c2592.64,3739.78) 2592.64,3747.66 2603.31,3747.66 cw(c2603.31,3739.78) 2607.73,3746.3 cw(c2603.31,3739.78) 2610.63,3742.7 ccw(c2621.6,3747.07) 2613.25,3738.71 ccw(c2621.6,3747.07) 2621.4,3735.26 ccw(c2621.21,3747.07) 2629.56,3738.71 ccw(c2621.21,3747.07) 2633.02,3747.07 2633.02,3767.93 ccw(c2621.21,3767.93) 2629.56,3776.28 ccw(c2621.21,3767.93) 2621.4,3779.74 ccw(c2621.6,3767.93) 2613.25,3776.28 ccw(c2621.6,3767.93) 2610.63,3772.3 cw(c2603.31,3775.22) 2607.73,3768.7 cw(c2603.31,3775.21) 2603.31,3767.34 2592.64,3767.34 cw(c2592.64,3775.22) 2588.22,3768.7 cw(c2592.64,3775.22) 2585.33,3772.3 ccw(c2574.36,3767.93) 2582.71,3776.28 ccw(c2574.36,3767.93) 2574.55,3779.74 ccw(c2574.75,3767.93) 2566.4,3776.28 ccw(c2574.75,3767.93) 2562.94,3767.93 2562.94,3747.07 ccw(c2574.75,3747.07) 2562.96,3746.38 ccw(c2574.75,3747.07)
cut-out: 2464.04,3764.3 cw(c2472.39,3772.66) 2460.58,3772.46 cw(c2472.39,3772.26) 2464.04,3780.61 cw(c2472.39,3772.26) 2468.02,3783.24 ccw(c2465.1,3790.55) 2471.62,3786.13 ccw(c2465.1,3790.55) 2472.98,3790.55 2472.98,3801.22 ccw(c2465.1,3801.22) 2471.62,3805.64 ccw(c2465.1,3801.22) 2468.02,3808.53 cw(c2472.39,3819.51) 2464.04,3811.16 cw(c2472.39,3819.51) 2460.58,3819.31 cw(c2472.39,3819.11) 2464.04,3827.47 cw(c2472.39,3819.11) 2472.39,3830.92 2493.25,3830.92 cw(c2493.25,3819.11) 2501.61,3827.47 cw(c2493.25,3819.11) 2505.06,3819.31 cw(c2493.25,3819.51) 2501.61,3811.16 cw(c2493.25,3819.51) 2497.62,3808.53 ccw(c2500.54,3801.22) 2494.02,3805.64 ccw(c2500.54,3801.22) 2492.66,3801.22 2492.66,3790.55 ccw(c2500.54,3790.55) 2494.02,3786.13 ccw(c2500.54,3790.55) 2497.62,3783.24 cw(c2493.26,3772.26) 2501.61,3780.61 cw(c2493.25,3772.26) 2505.06,3772.46 cw(c2493.25,3772.66) 2501.61,3764.3 cw(c2493.25,3772.66) 2493.94,3760.87 cw(c2493.25,3772.66) 2493.25,3760.85 2472.39,3760.85 cw(c2472.39,3772.66)
cut-out: 2336.08,3764.31 ccw(c2344.43,3772.66) 2344.24,3760.85 ccw(c2344.04,3772.66) 2352.39,3764.31 ccw(c2344.04,3772.66) 2355.01,3768.29 cw(c2362.33,3765.37) 2357.91,3771.89 cw(c2362.33,3765.37) 2362.33,3773.25 2373,3773.25 cw(c2373,3765.37) 2377.42,3771.89 cw(c2373,3765.37) 2380.31,3768.29 ccw(c2391.28,3772.66) 2382.93,3764.31 ccw(c2391.29,3772.66) 2391.09,3760.85 ccw(c2390.89,3772.66) 2399.24,3764.31 ccw(c2390.89,3772.66) 2402.7,3772.66 2402.7,3793.52 ccw(c2390.89,3793.52) 2399.24,3801.87 ccw(c2390.89,3793.52) 2391.09,3805.33 ccw(c2391.28,3793.52) 2382.93,3801.87 ccw(c2391.29,3793.52) 2380.31,3797.89 cw(c2373,3800.81) 2377.42,3794.29 cw(c2373,3800.81) 2373,3792.93 2362.33,3792.93 cw(c2362.33,3800.81) 2357.91,3794.29 cw(c2362.33,3800.81) 2355.01,3797.89 ccw(c2344.04,3793.52) 2352.39,3801.87 ccw(c2344.04,3793.52) 2344.24,3805.33 ccw(c2344.43,3793.52) 2336.08,3801.87 ccw(c2344.43,3793.52) 2332.62,3793.52 2332.62,3772.66 ccw(c2344.43,3772.66) 2332.64,3771.97 ccw(c2344.43,3772.66)

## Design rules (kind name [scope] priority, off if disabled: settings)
AcuteAngle [All] p1: minimum=4.50000000000000E+0001 checktracksonly=TRUE
AssemblyTestPointUsage [All] p1: valid=2
BoardOutlineClearance USB_CONN [InComponent('J8')or InComponent('J10')] p1: gap=80 ignorepadtopadclearanceinfootprint=FALSE except(0: THPad-OutlineEdge Text-OutlineEdge Text-CavityEdge Text-CutoutEdge Text-SplitBarrior Text-SplitContinuation; 16: Track-CutoutEdge; 19: SMDPad-OutlineEdge Fill-OutlineEdge; 30: Arc-OutlineEdge Track-OutlineEdge Via-OutlineEdge Poly-OutlineEdge Region-OutlineEdge)
BoardOutlineClearance DogBone [WithinRoom('BGA')] p2: gap=7 ignorepadtopadclearanceinfootprint=FALSE except(0: Arc-SplitContinuation Track-SplitContinuation SMDPad-SplitContinuation THPad-SplitContinuation Via-SplitContinuation Fill-SplitContinuation Poly-OutlineEdge Poly-CavityEdge Poly-CutoutEdge Poly-SplitBarrior Poly-SplitContinuation Region-OutlineEdge Region-CavityEdge Region-CutoutEdge Region-SplitBarrior Region-SplitContinuation Text-SplitContinuation)
BoardOutlineClearance BoardOutlineClearance_MountingHoles [OnCopper and InComponentClass('Mounting Holes')] p3: gap=39.37 ignorepadtopadclearanceinfootprint=FALSE
BoardOutlineClearance BoardOutlineClearance_Poly [OnCopper and IsPoly] p4: gap=30 ignorepadtopadclearanceinfootprint=FALSE
BoardOutlineClearance [OnCopper and Not InComponentClass('Logo') and not InComponentClass('FiducialMark')and not InComponentClass('RA PARTS') and not InPoly] p5: gap=80 ignorepadtopadclearanceinfootprint=FALSE except(0: THPad-OutlineEdge Text-OutlineEdge Text-CavityEdge Text-CutoutEdge Text-SplitBarrior Text-SplitContinuation; 16: Track-CutoutEdge; 19: Fill-OutlineEdge; 30: Arc-OutlineEdge Track-OutlineEdge SMDPad-OutlineEdge Via-OutlineEdge Poly-OutlineEdge Region-OutlineEdge)
Clearance Dogbone_BGA [WithinRoom('BGA') and IsTrack vs (OnLayer('SIG1') OR OnLayer('SIG2'))] p1: gap=6 ignorepadtopadclearanceinfootprint=TRUE
Clearance 0.65MM_BGA [WithinRoom('BGA') vs OnLayer('Bottom Layer')] p2: gap=4 ignorepadtopadclearanceinfootprint=TRUE except(0: Poly-Region Poly-Hole; 3.6: SMDPad-Via; 3.86: Track-SMDPad; 3.9: Arc-SMDPad; 6: Via-Via; 7: Via-Hole; 8: Arc-Hole Track-Poly SMDPad-SMDPad SMDPad-Fill SMDPad-Poly SMDPad-Hole Fill-Hole Region-Hole Text-Hole; 12: Arc-THPad Track-THPad SMDPad-THPad THPad-THPad THPad-Via THPad-Fill THPad-Poly THPad-Region THPad-Hole; 20: Fill-Fill Fill-Poly Poly-Poly Region-Region)
Clearance Clearance_Keepouts [IsKeepOut] p3: gap=1 ignorepadtopadclearanceinfootprint=FALSE
Clearance DIFF_100E_INT_same [(InNetClass('LVDS') or InNetClass('CSI'))and(OnLayer ('sig1') OR OnLayer('SIG2'))] p4: gap=8 ignorepadtopadclearanceinfootprint=TRUE except(1: Arc-Text Track-Text SMDPad-Text THPad-Text Via-Text Fill-Text Poly-Text Region-Text Text-Text; 6: Arc-Via Track-Via Via-Fill Via-Poly Via-Region; 7.2: Arc-Arc Arc-Track Track-Track; 9.5: Arc-Hole Track-Hole; 10: Via-Via Via-Hole Fill-Hole Poly-Hole Region-Hole; 12: Arc-THPad Track-THPad SMDPad-THPad SMDPad-Hole THPad-THPad THPad-Via THPad-Fill THPad-Poly THPad-Region THPad-Hole; 25: Fill-Fill Fill-Poly Fill-Region Poly-Poly Poly-Region Region-Region)
Clearance DIFF_100E_SAME [InDifferentialPairClass('DIFF_100E')and(OnLayer('Top Layer') OR OnLayer('Bottom Layer'))] p5: gap=8 ignorepadtopadclearanceinfootprint=TRUE except(1: Arc-Text Track-Text SMDPad-Text THPad-Text Via-Text Fill-Text Poly-Text Region-Text Text-Text; 5.4: Arc-Arc Arc-Track Track-Track; 6: Via-Fill Via-Poly Via-Region; 9.5: Arc-Hole Track-Hole; 10: SMDPad-Fill SMDPad-Poly SMDPad-Region Via-Via Via-Hole Fill-Hole Poly-Hole Region-Hole; 12: Arc-THPad Track-THPad SMDPad-THPad SMDPad-Hole THPad-THPad THPad-Via THPad-Fill THPad-Poly THPad-Region THPad-Hole; 25: Fill-Fill Fill-Poly Fill-Region Poly-Poly Poly-Region Region-Region)
Clearance DIFF_100E_EXT [InDifferentialPairClass('DIFF_100E')and(OnLayer('Top Layer') OR OnLayer('Bottom Layer'))] p6: gap=8 ignorepadtopadclearanceinfootprint=TRUE except(1: Arc-Text Track-Text SMDPad-Text THPad-Text Via-Text Fill-Text Poly-Text Region-Text Text-Text; 4: Track-Track; 4.19: Arc-Via; 6: Track-SMDPad Track-Via Via-Fill Via-Poly Via-Region; 7: Arc-Arc Arc-Track; 9.5: Arc-Hole Track-Hole; 10: SMDPad-Fill SMDPad-Poly SMDPad-Region Via-Via Via-Hole Fill-Poly Fill-Hole Poly-Hole Region-Hole; 12: Arc-THPad Track-THPad SMDPad-THPad SMDPad-Hole THPad-THPad THPad-Via THPad-Fill THPad-Poly THPad-Region THPad-Hole; 25: Fill-Fill Fill-Region Poly-Poly Poly-Region Region-Region)
Clearance DIFF_100E_INT [(InNetClass('LVDS') or InNetClass('CSI'))and(OnLayer ('sig1') OR OnLayer('SIG2'))] p7: gap=8 ignorepadtopadclearanceinfootprint=TRUE except(1: Arc-Text Track-Text SMDPad-Text THPad-Text Via-Text Fill-Text Poly-Text Region-Text Text-Text; 6: Arc-Via Track-Via Via-Fill Via-Poly Via-Region; 9.5: Arc-Hole Track-Hole; 10: Via-Via Via-Hole Fill-Hole Poly-Hole Region-Hole; 12: Arc-THPad Track-THPad SMDPad-THPad SMDPad-Hole THPad-THPad THPad-Via THPad-Fill THPad-Poly THPad-Region THPad-Hole; 14.6: Arc-Arc Arc-Track Track-Track; 25: Fill-Fill Fill-Poly Fill-Region Poly-Poly Poly-Region Region-Region)
Clearance DIFF_90E_EXT_SAME [InDifferentialPairClass('DIFF_90E')and(OnLayer('Top Layer') OR OnLayer('Bottom Layer'))] p8: gap=8 ignorepadtopadclearanceinfootprint=TRUE except(1: Arc-Text Track-Text SMDPad-Text THPad-Text Via-Text Fill-Text Poly-Text Region-Text Text-Text; 4.55: Track-Track; 5: Arc-Via; 6: Track-SMDPad Track-Via Via-Fill Via-Poly Via-Region; 7: Arc-Arc Arc-Track; 9.5: Arc-Hole Track-Hole; 10: SMDPad-Fill SMDPad-Poly SMDPad-Region Via-Hole Fill-Poly Fill-Hole Poly-Hole Region-Hole; 12: Arc-THPad Track-THPad SMDPad-THPad SMDPad-Hole THPad-THPad THPad-Via THPad-Fill THPad-Poly THPad-Region THPad-Hole; 25: Fill-Fill Fill-Region Poly-Poly Poly-Region Region-Region)
Clearance DIFF_90E_EXT [InDifferentialPairClass('DIFF_90E')and(OnLayer('Top Layer') OR OnLayer('Bottom Layer'))] p9: gap=8 ignorepadtopadclearanceinfootprint=TRUE except(1: Arc-Text Track-Text SMDPad-Text THPad-Text Via-Text Fill-Text Poly-Text Region-Text Text-Text; 5: Arc-Via; 6: Track-SMDPad Track-Via Via-Fill Via-Poly Via-Region; 7: Arc-Arc Arc-Track; 9.5: Arc-Hole Track-Hole; 10: SMDPad-Fill SMDPad-Poly SMDPad-Region Via-Via Via-Hole Fill-Poly Fill-Hole Poly-Hole Region-Hole; 12: Arc-THPad Track-THPad SMDPad-THPad SMDPad-Hole THPad-THPad THPad-Via THPad-Fill THPad-Poly THPad-Region THPad-Hole; 13.4: Track-Track; 25: Fill-Fill Fill-Region Poly-Poly Poly-Region Region-Region)
Clearance DIFF_90E_INT [InDifferentialPairClass('DIFF_90E')and(OnLayer('SIG1') OR OnLayer('SIG2'))] p10: gap=8 ignorepadtopadclearanceinfootprint=TRUE except(1: Arc-Text Track-Text SMDPad-Text THPad-Text Via-Text Fill-Text Poly-Text Region-Text Text-Text; 5: Arc-Via; 6: Track-Via Via-Fill Via-Poly Via-Region; 9.5: Arc-Hole Track-Hole; 10: SMDPad-Fill SMDPad-Poly SMDPad-Region Via-Via Via-Hole Fill-Poly Fill-Hole Poly-Hole Region-Hole; 12: Arc-THPad Track-THPad SMDPad-THPad SMDPad-Hole THPad-THPad THPad-Via THPad-Fill THPad-Poly THPad-Region THPad-Hole; 15: Arc-Arc Arc-Track Track-Track; 25: Fill-Fill Fill-Region Poly-Poly Poly-Region Region-Region)
Clearance 2W_50E_INT [InNetClass('RGMII_TX_RX')and(OnLayer('SIG1') OR OnLayer('SIG2'))] p11: gap=8 ignorepadtopadclearanceinfootprint=TRUE except(1: Arc-Text Track-Text SMDPad-Text THPad-Text Via-Text Fill-Text Poly-Text Region-Text Text-Text; 5: Arc-Via Track-Via; 5.5: Arc-Arc; 6: Via-Fill Via-Poly Via-Region; 9.5: Arc-Hole Track-Hole; 10: Arc-THPad Track-THPad SMDPad-Fill SMDPad-Poly SMDPad-Region Via-Hole Fill-Poly Fill-Hole Poly-Hole Region-Hole; 11: Arc-Track Track-Track; 12: SMDPad-THPad SMDPad-Hole THPad-THPad THPad-Via THPad-Fill THPad-Poly THPad-Region THPad-Hole; 18: Via-Via; 25: Fill-Fill Fill-Region Poly-Poly Poly-Region Region-Region)
Clearance Clearance_CNTRL [WithinRoom('RouteCNTRL') vs OnLayer('Bottom Layer')] p12: gap=8 ignorepadtopadclearanceinfootprint=TRUE except(0: Poly-Region; 4: Track-Hole; 5.5: Arc-Arc Arc-Track Track-Track; 6: Arc-SMDPad Arc-Via Track-SMDPad Track-Via Via-Poly; 10: Arc-Hole Via-Hole Fill-Hole Poly-Hole Region-Hole; 12: SMDPad-THPad SMDPad-Hole THPad-THPad THPad-Via THPad-Fill THPad-Poly THPad-Region THPad-Hole; 18: Fill-Fill Fill-Poly Fill-Region Poly-Poly Region-Region)
Clearance Clearance_AGND [InNamedPolygon('Top Layer-AGND 1')] p13: gap=10 ignorepadtopadclearanceinfootprint=FALSE except(0: Arc-Hole Track-Hole SMDPad-Hole THPad-Hole Via-Hole Fill-Hole Poly-Hole Region-Hole Text-Hole)
Clearance Clearance_Poly_INT [InPolygon vs OnLayer('PWR1') OR OnLayer('PWR2')] p14: gap=20 ignorepadtopadclearanceinfootprint=TRUE except(5: Arc-Text Track-Text SMDPad-Text THPad-Text Via-Text Fill-Text Poly-Text Region-Text Text-Text; 6: Arc-Via Track-Via SMDPad-Fill SMDPad-Poly SMDPad-Region; 8: Arc-Arc Arc-Track Arc-SMDPad Track-Track Track-SMDPad SMDPad-Via THPad-Via THPad-Fill THPad-Poly THPad-Region Text-Hole; 10: Arc-THPad Arc-Hole Track-THPad Track-Hole Via-Fill Via-Poly Via-Region Via-Hole Fill-Hole Poly-Hole Region-Hole; 12: SMDPad-SMDPad SMDPad-THPad SMDPad-Hole THPad-THPad THPad-Hole Via-Via)
Clearance Clearance_FiducialMark [IsKeepOut and InComponentClass('FiducialMark') vs IsPad and InComponentClass('FiducialMark')] p15: gap=0 ignorepadtopadclearanceinfootprint=FALSE
Clearance Clearance_TOP [All and (not InAnyDifferentialPair) vs OnLayer('Top Layer')] p16: gap=8 ignorepadtopadclearanceinfootprint=TRUE except(0: Poly-Region; 1: Arc-Text Track-Text SMDPad-Text THPad-Text Via-Text Fill-Text Poly-Text Region-Text Text-Text; 5: Arc-Via Track-Via; 6: Via-Fill Via-Poly Via-Region; 7: Arc-Arc Arc-Track Arc-SMDPad Track-Track Track-SMDPad; 9: Arc-Hole Track-Hole; 10: Via-Via Via-Hole Fill-Hole Poly-Hole Region-Hole; 12: SMDPad-THPad SMDPad-Hole THPad-THPad THPad-Via THPad-Fill THPad-Poly THPad-Region THPad-Hole; 18: Fill-Fill Fill-Poly Fill-Region Poly-Poly Region-Region)
Clearance Clearance_U8 [WithinRoom('U6_') and IsTrack vs OnLayer('Bottom Layer')] p17: gap=8 ignorepadtopadclearanceinfootprint=TRUE except(1: Arc-Text Track-Text SMDPad-Text THPad-Text Via-Text Fill-Text Poly-Text Region-Text Text-Text; 4: Arc-Hole Track-Track Track-Hole SMDPad-Hole THPad-Hole Via-Hole Fill-Hole Poly-Hole Region-Hole Text-Hole; 5: Arc-Via Track-Via; 6: SMDPad-Via THPad-Via Via-Fill Via-Poly Via-Region; 7: Arc-Arc Arc-Track Arc-SMDPad Track-SMDPad; 10: Via-Via; 12: SMDPad-THPad THPad-THPad THPad-Fill THPad-Poly THPad-Region; 18: Fill-Fill Fill-Poly Fill-Region Poly-Poly Poly-Region Region-Region)
Clearance Clearance_SOLD [All and (not InAnyDifferentialPair) vs OnLayer('Bottom Layer')] p18: gap=8 ignorepadtopadclearanceinfootprint=TRUE except(1: Arc-Text Track-Text SMDPad-Text THPad-Text Via-Text Fill-Text Poly-Text Region-Text Text-Text; 5: Arc-Via Track-Via; 6: Via-Fill Via-Poly Via-Region; 7: Arc-Arc Arc-Track Arc-SMDPad Track-Track Track-SMDPad; 9: Arc-Hole Track-Hole; 10: Via-Via Via-Hole Fill-Hole Poly-Hole Region-Hole; 12: SMDPad-THPad SMDPad-Hole THPad-THPad THPad-Via THPad-Fill THPad-Poly THPad-Region THPad-Hole; 18: Fill-Fill Fill-Poly Fill-Region Poly-Region Region-Region; 20: Poly-Poly)
Clearance Clearance_Poly_EXT [(InNetClass('PWR') AND OnLayer('Top Layer') AND ('Bottom Layer'))] p19: gap=12 ignorepadtopadclearanceinfootprint=TRUE except(1: Arc-Text Track-Text SMDPad-Text THPad-Text Via-Text Fill-Text Poly-Text Region-Text Text-Text Text-Hole; 6: Via-Fill Via-Poly Via-Region; 8: Arc-Arc Arc-Track Arc-SMDPad Track-Track Track-SMDPad SMDPad-SMDPad SMDPad-Via; 10: Arc-Via Arc-Hole Track-Via Track-Hole Via-Hole Fill-Hole Poly-Hole Region-Hole; 18: Via-Via Fill-Fill Fill-Poly Fill-Region Poly-Poly Poly-Region Region-Region)
Clearance [All] p20: gap=8 ignorepadtopadclearanceinfootprint=TRUE except(0: Poly-Region; 6: Arc-Arc Arc-Track Arc-Via Track-Track Track-Via Via-Fill Via-Poly Via-Region; 10: Arc-Hole Track-Hole Via-Hole Fill-Hole Poly-Hole Region-Hole; 12: SMDPad-THPad SMDPad-Hole THPad-THPad THPad-Via THPad-Fill THPad-Poly THPad-Region THPad-Hole; 18: Fill-Fill Fill-Poly Fill-Region Poly-Poly Region-Region)
ComponentClearance TRIPAD [InComponent('R192') or InComponent('R196')] p1: gap=0 collisioncheckmode=3 verticalgap=0 showdistances=FALSE
ComponentClearance U*_Clearance [WithinRoom('U8')] p2: gap=0 collisioncheckmode=3 verticalgap=0 showdistances=FALSE
ComponentClearance ComponentClearance_MountingHoles_FiducialMarks [InComponentClass('Mounting Holes') vs InComponentClass('FiducialMark')] p3: gap=50 collisioncheckmode=3 verticalgap=10 showdistances=FALSE
ComponentClearance ComponentClearance_Shunt [InComponentClass('Header') vs InComponentClass('Shunt')] p4: gap=0 collisioncheckmode=3 verticalgap=0 showdistances=FALSE
ComponentClearance ComponentClearance_Logo [InComponentClass('Logo')] p5: gap=10 collisioncheckmode=3 verticalgap=10 showdistances=FALSE
ComponentClearance ComponentClearance_ScrewToNut [(HasFootprint('NY PMS 440 0025 PH')) vs (HasFootprint('Keystone_1902C'))] p6: gap=5 collisioncheckmode=3 verticalgap=10 showdistances=FALSE
ComponentClearance ComponentClearance_MountingHoles [InComponentClass('Mounting Holes')] p7: gap=250 collisioncheckmode=3 verticalgap=100000 showdistances=FALSE
ComponentClearance ComponentClearance_SmallPassives [HasFootprint('0201*') or  HasFootprint('0508') or HasFootprint('0603*') or HasFootprint('0612') or HasFootprint('0805*') or HasFootprint('0815*') or HasFootprint('0830*') or HasFootprint('1206*') or HasFootprint('1210*') or HasFootprint('1808*') or HasFootprint('1812*') or HasFootprint('1825*') or HasFootprint('2010*') or HasFootprint('2220*') or HasFootprint('2225*') or HasFootprint('2512*') or HasFootprint('2728*') or HasFootprint('3518*') vs HasFootprint('0201*') or HasFootprint('0508') or HasFootprint('0603*') or HasFootprint('0612') or HasFootprint('0805*') or HasFootprint('0815*') or HasFootprint('0830*') or HasFootprint('1206*') or HasFootprint('1210*') or HasFootprint('1808*') or HasFootprint('1812*') or HasFootprint('1825*') or HasFootprint('2010*') or HasFootprint('2220*') or HasFootprint('2225*') or HasFootprint('2512*') or HasFootprint('2728*') or HasFootprint('3518*')] p8: gap=0 collisioncheckmode=3 verticalgap=5 showdistances=FALSE
ComponentClearance ComponentClearance_THtoSMT [IsThruComponent vs IsSMTComponent] p9: gap=10 collisioncheckmode=3 verticalgap=10 showdistances=FALSE
ComponentClearance ComponentClearance_THtoTH [IsThruComponent vs IsThruComponent] p10: gap=20 collisioncheckmode=3 verticalgap=10 showdistances=FALSE
ComponentClearance "TRIPAD COMPONENTS" [InComponentClass('TRIPAD RESISTORS')] p11: gap=0 collisioncheckmode=3 verticalgap=0 showdistances=FALSE
ComponentClearance [All] p12: gap=10 collisioncheckmode=3 verticalgap=0 showdistances=FALSE
DiffPairsRouting DiffPairsRouting_100E [InDifferentialPairClass('DIFF_100E')] p1: maxlimit=7.2 minlimit=1 mostfreqgap=7.2 toplayer_mingap=5.4 toplayer_maxgap=5.4 toplayer_prefgap=5.4 toplayer_minwidth=4.8 toplayer_maxwidth=4.8 toplayer_prefwidth=4.8 midlayer2_maxgap=1 midlayer2_prefgap=1 midlayer2_minwidth=1 midlayer2_maxwidth=1 midlayer2_prefwidth=1 midlayer3_maxgap=1 midlayer3_prefgap=1 midlayer3_minwidth=1 midlayer3_maxwidth=1 midlayer3_prefwidth=1 midlayer5_maxgap=1 midlayer5_prefgap=1 midlayer5_minwidth=1 midlayer5_maxwidth=1 midlayer5_prefwidth=1 midlayer6_mingap=7.2 midlayer6_minwidth=4.8 midlayer6_maxwidth=4.8 midlayer6_prefwidth=4.8 midlayer7_mingap=7.2 midlayer7_minwidth=4.8 midlayer7_maxwidth=4.8 midlayer7_prefwidth=4.8 midlayer8_maxgap=1 midlayer8_prefgap=1 midlayer8_minwidth=1 midlayer8_maxwidth=1 midlayer8_prefwidth=1 bottomlayer_mingap=5.4 bottomlayer_maxgap=5.4 bottomlayer_prefgap=5.4 bottomlayer_minwidth=4.8 bottomlayer_maxwidth=4.8 bottomlayer_prefwidth=4.8 substack1={9319A519-0D26-40B3-8AF8-C4998BECF1C7} toplayer_{9319a519-0d26-40b3-8af8-c4998becf1c7}_mingap=10 toplayer_{9319a519-0d26-40b3-8af8-c4998becf1c7}_maxgap=10 toplayer_{9319a519-0d26-40b3-8af8-c4998becf1c7}_prefgap=10 toplayer_{9319a519-0d26-40b3-8af8-c4998becf1c7}_minwidth=15 toplayer_{9319a519-0d26-40b3-8af8-c4998becf1c7}_maxwidth=15 toplayer_{9319a519-0d26-40b3-8af8-c4998becf1c7}_prefwidth=15 midlayer2_{9319a519-0d26-40b3-8af8-c4998becf1c7}_mingap=10 midlayer2_{9319a519-0d26-40b3-8af8-c4998becf1c7}_maxgap=10 midlayer2_{9319a519-0d26-40b3-8af8-c4998becf1c7}_prefgap=10 midlayer2_{9319a519-0d26-40b3-8af8-c4998becf1c7}_minwidth=15 midlayer2_{9319a519-0d26-40b3-8af8-c4998becf1c7}_maxwidth=15 midlayer2_{9319a519-0d26-40b3-8af8-c4998becf1c7}_prefwidth=15 midlayer3_{9319a519-0d26-40b3-8af8-c4998becf1c7}_mingap=10 midlayer3_{9319a519-0d26-40b3-8af8-c4998becf1c7}_maxgap=10 midlayer3_{9319a519-0d26-40b3-8af8-c4998becf1c7}_prefgap=10 midlayer3_{9319a519-0d26-40b3-8af8-c4998becf1c7}_minwidth=15 midlayer3_{9319a519-0d26-40b3-8af8-c4998becf1c7}_maxwidth=15 midlayer3_{9319a519-0d26-40b3-8af8-c4998becf1c7}_prefwidth=15 midlayer5_{9319a519-0d26-40b3-8af8-c4998becf1c7}_mingap=10 midlayer5_{9319a519-0d26-40b3-8af8-c4998becf1c7}_maxgap=10 midlayer5_{9319a519-0d26-40b3-8af8-c4998becf1c7}_prefgap=10 midlayer5_{9319a519-0d26-40b3-8af8-c4998becf1c7}_minwidth=15 midlayer5_{9319a519-0d26-40b3-8af8-c4998becf1c7}_maxwidth=15 midlayer5_{9319a519-0d26-40b3-8af8-c4998becf1c7}_prefwidth=15 midlayer6_{9319a519-0d26-40b3-8af8-c4998becf1c7}_mingap=10 midlayer6_{9319a519-0d26-40b3-8af8-c4998becf1c7}_maxgap=10 midlayer6_{9319a519-0d26-40b3-8af8-c4998becf1c7}_prefgap=10 midlayer6_{9319a519-0d26-40b3-8af8-c4998becf1c7}_minwidth=15 midlayer6_{9319a519-0d26-40b3-8af8-c4998becf1c7}_maxwidth=15 midlayer6_{9319a519-0d26-40b3-8af8-c4998becf1c7}_prefwidth=15 midlayer7_{9319a519-0d26-40b3-8af8-c4998becf1c7}_mingap=10 midlayer7_{9319a519-0d26-40b3-8af8-c4998becf1c7}_maxgap=10 midlayer7_{9319a519-0d26-40b3-8af8-c4998becf1c7}_prefgap=10 midlayer7_{9319a519-0d26-40b3-8af8-c4998becf1c7}_minwidth=15 midlayer7_{9319a519-0d26-40b3-8af8-c4998becf1c7}_maxwidth=15 midlayer7_{9319a519-0d26-40b3-8af8-c4998becf1c7}_prefwidth=15 midlayer8_{9319a519-0d26-40b3-8af8-c4998becf1c7}_mingap=10 midlayer8_{9319a519-0d26-40b3-8af8-c4998becf1c7}_maxgap=10 midlayer8_{9319a519-0d26-40b3-8af8-c4998becf1c7}_prefgap=10 midlayer8_{9319a519-0d26-40b3-8af8-c4998becf1c7}_minwidth=15 midlayer8_{9319a519-0d26-40b3-8af8-c4998becf1c7}_maxwidth=15 midlayer8_{9319a519-0d26-40b3-8af8-c4998becf1c7}_prefwidth=15 bottomlayer_{9319a519-0d26-40b3-8af8-c4998becf1c7}_mingap=10 bottomlayer_{9319a519-0d26-40b3-8af8-c4998becf1c7}_maxgap=10 bottomlayer_{9319a519-0d26-40b3-8af8-c4998becf1c7}_prefgap=10 bottomlayer_{9319a519-0d26-40b3-8af8-c4998becf1c7}_minwidth=15 bottomlayer_{9319a519-0d26-40b3-8af8-c4998becf1c7}_maxwidth=15 bottomlayer_{9319a519-0d26-40b3-8af8-c4998becf1c7}_prefwidth=15 filterlayerstackid={9F2BDCAB-BF4A-4FAE-9F57-695CEC5DA6CF} maxuncoupledlength=230
DiffPairsRouting DiffPairsRouting_90E [InDifferentialPairClass('DIFF_90E')] p2: maxlimit=6.2 minlimit=1 mostfreqgap=6.2 toplayer_mingap=4.55 toplayer_maxgap=4.55 toplayer_prefgap=4.55 toplayer_minwidth=5.65 toplayer_maxwidth=5.65 toplayer_prefwidth=5.65 midlayer2_maxgap=1 midlayer2_prefgap=1 midlayer2_minwidth=1 midlayer2_maxwidth=1 midlayer2_prefwidth=1 midlayer3_maxgap=1 midlayer3_prefgap=1 midlayer3_minwidth=1 midlayer3_maxwidth=1 midlayer3_prefwidth=1 midlayer5_maxgap=1 midlayer5_prefgap=1 midlayer5_minwidth=1 midlayer5_maxwidth=1 midlayer5_prefwidth=1 midlayer6_mingap=6.2 midlayer6_minwidth=5.8 midlayer6_maxwidth=5.8 midlayer6_prefwidth=5.8 midlayer7_mingap=6.2 midlayer7_minwidth=5.8 midlayer7_maxwidth=5.8 midlayer7_prefwidth=5.8 midlayer8_maxgap=1 midlayer8_prefgap=1 midlayer8_minwidth=1 midlayer8_maxwidth=1 midlayer8_prefwidth=1 bottomlayer_mingap=4.55 bottomlayer_maxgap=4.55 bottomlayer_prefgap=4.55 bottomlayer_minwidth=5.65 bottomlayer_maxwidth=5.65 bottomlayer_prefwidth=5.65 substack1={9319A519-0D26-40B3-8AF8-C4998BECF1C7} toplayer_{9319a519-0d26-40b3-8af8-c4998becf1c7}_mingap=10 toplayer_{9319a519-0d26-40b3-8af8-c4998becf1c7}_maxgap=10 toplayer_{9319a519-0d26-40b3-8af8-c4998becf1c7}_prefgap=10 toplayer_{9319a519-0d26-40b3-8af8-c4998becf1c7}_minwidth=15 toplayer_{9319a519-0d26-40b3-8af8-c4998becf1c7}_maxwidth=15 toplayer_{9319a519-0d26-40b3-8af8-c4998becf1c7}_prefwidth=15 midlayer2_{9319a519-0d26-40b3-8af8-c4998becf1c7}_mingap=10 midlayer2_{9319a519-0d26-40b3-8af8-c4998becf1c7}_maxgap=10 midlayer2_{9319a519-0d26-40b3-8af8-c4998becf1c7}_prefgap=10 midlayer2_{9319a519-0d26-40b3-8af8-c4998becf1c7}_minwidth=15 midlayer2_{9319a519-0d26-40b3-8af8-c4998becf1c7}_maxwidth=15 midlayer2_{9319a519-0d26-40b3-8af8-c4998becf1c7}_prefwidth=15 midlayer3_{9319a519-0d26-40b3-8af8-c4998becf1c7}_mingap=10 midlayer3_{9319a519-0d26-40b3-8af8-c4998becf1c7}_maxgap=10 midlayer3_{9319a519-0d26-40b3-8af8-c4998becf1c7}_prefgap=10 midlayer3_{9319a519-0d26-40b3-8af8-c4998becf1c7}_minwidth=15 midlayer3_{9319a519-0d26-40b3-8af8-c4998becf1c7}_maxwidth=15 midlayer3_{9319a519-0d26-40b3-8af8-c4998becf1c7}_prefwidth=15 midlayer5_{9319a519-0d26-40b3-8af8-c4998becf1c7}_mingap=10 midlayer5_{9319a519-0d26-40b3-8af8-c4998becf1c7}_maxgap=10 midlayer5_{9319a519-0d26-40b3-8af8-c4998becf1c7}_prefgap=10 midlayer5_{9319a519-0d26-40b3-8af8-c4998becf1c7}_minwidth=15 midlayer5_{9319a519-0d26-40b3-8af8-c4998becf1c7}_maxwidth=15 midlayer5_{9319a519-0d26-40b3-8af8-c4998becf1c7}_prefwidth=15 midlayer6_{9319a519-0d26-40b3-8af8-c4998becf1c7}_mingap=10 midlayer6_{9319a519-0d26-40b3-8af8-c4998becf1c7}_maxgap=10 midlayer6_{9319a519-0d26-40b3-8af8-c4998becf1c7}_prefgap=10 midlayer6_{9319a519-0d26-40b3-8af8-c4998becf1c7}_minwidth=15 midlayer6_{9319a519-0d26-40b3-8af8-c4998becf1c7}_maxwidth=15 midlayer6_{9319a519-0d26-40b3-8af8-c4998becf1c7}_prefwidth=15 midlayer7_{9319a519-0d26-40b3-8af8-c4998becf1c7}_mingap=10 midlayer7_{9319a519-0d26-40b3-8af8-c4998becf1c7}_maxgap=10 midlayer7_{9319a519-0d26-40b3-8af8-c4998becf1c7}_prefgap=10 midlayer7_{9319a519-0d26-40b3-8af8-c4998becf1c7}_minwidth=15 midlayer7_{9319a519-0d26-40b3-8af8-c4998becf1c7}_maxwidth=15 midlayer7_{9319a519-0d26-40b3-8af8-c4998becf1c7}_prefwidth=15 midlayer8_{9319a519-0d26-40b3-8af8-c4998becf1c7}_mingap=10 midlayer8_{9319a519-0d26-40b3-8af8-c4998becf1c7}_maxgap=10 midlayer8_{9319a519-0d26-40b3-8af8-c4998becf1c7}_prefgap=10 midlayer8_{9319a519-0d26-40b3-8af8-c4998becf1c7}_minwidth=15 midlayer8_{9319a519-0d26-40b3-8af8-c4998becf1c7}_maxwidth=15 midlayer8_{9319a519-0d26-40b3-8af8-c4998becf1c7}_prefwidth=15 bottomlayer_{9319a519-0d26-40b3-8af8-c4998becf1c7}_mingap=10 bottomlayer_{9319a519-0d26-40b3-8af8-c4998becf1c7}_maxgap=10 bottomlayer_{9319a519-0d26-40b3-8af8-c4998becf1c7}_prefgap=10 bottomlayer_{9319a519-0d26-40b3-8af8-c4998becf1c7}_minwidth=15 bottomlayer_{9319a519-0d26-40b3-8af8-c4998becf1c7}_maxwidth=15 bottomlayer_{9319a519-0d26-40b3-8af8-c4998becf1c7}_prefwidth=15 maxuncoupledlength=200
FabricationTestPointUsage TestPointUsage [All] p1: valid=2 allowmultiple=FALSE
FabricationTestpoint Testpoint [All] p1: side=3 testpointundercomponent=TRUE minsize=40 maxsize=100 preferedsize=60 minholesize=0 maxholesize=40 preferedholesize=32 testpointgrid=1 allowsidetop=TRUE allowsidebottom=TRUE usegrid=TRUE gridtolerance=0.01
FanoutControl Fanout_LCC [IsLCC] p1: bgadir=Out bgaviamode=Centered fanoutstyle=Auto fanoutdirection=Alternating viagrid=1 // Fanout_LCC (Default Rule)
FanoutControl Fanout_BGA [IsBGA] p2: bgadir=Out bgaviamode=Centered fanoutstyle=Auto fanoutdirection=Alternating viagrid=1 // Fanout_BGA (Default Rule)
FanoutControl Fanout_Default [All] p4: bgadir=Out bgaviamode=Centered fanoutstyle=Auto fanoutdirection=Alternating viagrid=1 // Fanout_Default (Default Rule)
FanoutControl Fanout_Small [(CompPinCount < 5)] p5: bgadir=Out bgaviamode=Centered fanoutstyle=Auto fanoutdirection=OutThenIn viagrid=1 // Fanout_Small (Default Rule)
HoleSize [All] p1: absolutevalues=TRUE maxlimit=300 minlimit=4 maxpercent=80.000 minpercent=20.000
HoleToHoleClearance [All] p1: gap=5 allowstackedmicrovias=TRUE
MatchedLengths RGMII_TX [InxSignalClass('RGMII_Tx')] p1: tolerance=12.5 checknetsindiffpair=FALSE checkdiffpairvsdiffpair=TRUE checkxsignals=TRUE checkothers=TRUE
MatchedLengths Trace [InxSignalClass('Trace')] p2: tolerance=12.5 checknetsindiffpair=FALSE checkdiffpairvsdiffpair=TRUE checkxsignals=TRUE checkothers=TRUE
MatchedLengths DBG_SPI [InxSignalClass('DBG_SPI')] p3: tolerance=10 checknetsindiffpair=FALSE checkdiffpairvsdiffpair=TRUE checkxsignals=TRUE checkothers=TRUE
MatchedLengths PMIC_SPI [InxSignalClass('PMIC_SPI')] p4: tolerance=10 checknetsindiffpair=FALSE checkdiffpairvsdiffpair=TRUE checkxsignals=TRUE checkothers=TRUE
MatchedLengths QSPI [InxSignalClass('QSPI')] p5: tolerance=100 checknetsindiffpair=FALSE checkdiffpairvsdiffpair=TRUE checkxsignals=TRUE checkothers=TRUE
MatchedLengths PMIC_SPI_J16_1 [InxSignalClass('PMIC_SPI_J16')] p6: tolerance=100 checknetsindiffpair=FALSE checkdiffpairvsdiffpair=TRUE checkxsignals=TRUE checkothers=TRUE
MatchedLengths RGMII_RX [InxSignalClass('RGMII_Rx')] p7: tolerance=12.5 checknetsindiffpair=FALSE checkdiffpairvsdiffpair=TRUE checkxsignals=TRUE checkothers=TRUE
MatchedLengths RGMII_RX_DX [InxSignalClass('RX_DX')] p8: tolerance=12.5 checknetsindiffpair=FALSE checkdiffpairvsdiffpair=TRUE checkxsignals=TRUE checkothers=TRUE
MatchedLengths RGMII_TX_DX [InxSignalClass('TX_DX')] p9: tolerance=12.5 checknetsindiffpair=FALSE checkdiffpairvsdiffpair=TRUE checkxsignals=TRUE checkothers=TRUE
MatchedLengths Trace_Data [InxSignalClass('Trace')] p10: tolerance=50 checknetsindiffpair=FALSE checkdiffpairvsdiffpair=TRUE checkxsignals=TRUE checkothers=TRUE
MatchedLengths TD [InxSignalClass('TD')] p11: tolerance=12.5 checknetsindiffpair=FALSE checkdiffpairvsdiffpair=TRUE checkxsignals=TRUE checkothers=TRUE
MatchedLengths LVDS_diff [InDifferentialPairClass('LVDS')] p12: tolerance=2.5 checknetsindiffpair=TRUE checkdiffpairvsdiffpair=FALSE checkxsignals=FALSE checkothers=FALSE
MatchedLengths LVDS [InxSignalClass('LVDS_TX')] p13: tolerance=12.5 checknetsindiffpair=FALSE checkdiffpairvsdiffpair=TRUE checkxsignals=TRUE checkothers=TRUE
MatchedLengths CSI2 [InxSignalClass('CSI2')] p14: tolerance=12.5 checknetsindiffpair=FALSE checkdiffpairvsdiffpair=TRUE checkxsignals=TRUE checkothers=TRUE
MatchedLengths CSI2_DIFF [InxSignalClass('CSI2')] p15: tolerance=2.5 checknetsindiffpair=TRUE checkdiffpairvsdiffpair=FALSE checkxsignals=FALSE checkothers=FALSE
MinimumAnnularRing MinimumAnnularRing_ThermalPadVias [IsVia and InAnyComponent] p1: minimumring=5
MinimumAnnularRing [All] p2 off: minimumring=6
MinimumSolderMaskSliver MinimumSolderMaskSliver_Logo [InComponentClass('Logo') vs InComponentClass('Logo')] p1: minsoldermaskwidth=0.7
MinimumSolderMaskSliver [All] p2: minsoldermaskwidth=3
PlaneConnect [All] p1: planeconnectstyle=Relief reliefexpansion=10 reliefentries=4 reliefconductorwidth=10 reliefairgap=10
PolygonConnect [All] p1: connectstyle=Direct reliefconductorwidth=10 reliefentries=4 polygonreliefangle="90 Angle" airgapwidth=10
RoomDefinition U8 [False vs False] p1: confinementstyle=ConfineIn formatcopy=TRUE lockcomponents=FALSE outline 1353,1597.81 1605,1597.81 1605,1315.81 1353,1315.81
RoomDefinition RouteCNTRL [False] p2: confinementstyle=ConfineIn formatcopy=TRUE lockcomponents=FALSE outline 2625,3661.87 2218.62,3661.87 2218.62,4127.7 2744.66,4127.7 2744.66,3661.54 2630,3661.86 2630,3536.81 2925.19,3536.81 2925.19,4287 2825,4387.18 2100.37,4387.18 2050,4336.81 2050,3336.81 2125,3261.81 2625,3261.81
RoomDefinition U6_ [False] p3: confinementstyle=ConfineIn formatcopy=TRUE lockcomponents=FALSE outline 2107,1639.81 2925.31,1639.81 2925.31,1010.67 2107,1010.67
RoomDefinition BGA [False vs False] p4: confinementstyle=ConfineIn formatcopy=TRUE lockcomponents=FALSE outline 2217.96,4138.07 2777.67,4138.07 2777.67,3658.75 2217.96,3658.75
RoutingVias [All] p1: holewidth=8 width=18 viastyle="Through Hole" minholewidth=5.9 minwidth=13.77 maxholewidth=12 maxwidth=22 useviatemplates=TRUE viatemplateguid#1={DC25F805-5D65-404C-B501-52BE5CACCB3C} viatemplateguid#2={9ED9010B-0CDF-4524-9443-1256A615406B} viatemplateguid#3={4BD1C2A0-9719-4ED9-BA98-7C9EF7797C5E} viatemplateguid#4={7FF36575-4288-4E57-9996-29C1B4EF6CB1} viatemplateguid#5={598CEAA4-0619-4763-88C8-8C8E0D82E9DC} viatemplateguid#6={F7D588A1-9857-44E4-BFAD-FDA9B8594EB6} viatemplateguid#7={608DC227-D7D4-44EF-9655-D19E6AF18B4D} viatemplatename#1=v25h10m30mx0(Tol3-3) viatemplatename#2=v46h20m0mx0 viatemplatename#3=v46h20m0mx0(Tol8-8) viatemplatename#4=v50h20 viatemplatename#5=v50h20m0mx0 viatemplatename#6=v50h20m50 viatemplatename#7=v51h25m0mx0(Tol8-8)
SMDEntry [All] p1: side=TRUE corner=FALSE anyangle=TRUE
ShortCircuit DogBONE_Shorts [IsBoardCutoutRegion and WithinRoom('BGA')] p1: allowed=TRUE
ShortCircuit [All] p2: allowed=FALSE
SilkToBoardRegionClearance [Not ((IsComment or IsDesignator) And (Hide <> 'False')) and not InRegion(1000,500,4000,800)] p1:
SilkToSilkClearance SilkToSilkClearance_Pb-FreeLogo [(HasFootprint('Pb-Free_Overlay_Medium') OR HasFootprint('Pb-Free_Overlay_Small')) vs (HasFootprint('Pb-Free_Overlay_Medium') OR HasFootprint('Pb-Free_Overlay_Small'))] p1: silktosilkclearance=0
SilkToSilkClearance [All] p2: silktosilkclearance=0
SilkToSolderMaskClearance SilkToComponentPadClearance [(IsPad or IsFill or IsRegion) and InAnycomponent] p1: minsilkscreentomaskgap=3 clearancetoexposedcopper=TRUE
SilkToSolderMaskClearance "Silk to Solder Mask Opening" [All] p2: minsilkscreentomaskgap=3 clearancetoexposedcopper=FALSE
SolderMaskExpansion [All] p1: expansion=1.97 istentingtop=FALSE
UnRoutedNet [All] p1: checkbadconnections=TRUE
Width Width_Route_CNTRL [WithinRoom('BGA') or WithinRoom('RouteCNTRL')] p1: maxlimit=50 minlimit=4 preferedwidth=6 toplayer_prefwidth=4 midlayer2_minwidth=6 midlayer3_minwidth=6 midlayer5_minwidth=10 midlayer5_prefwidth=10 midlayer6_minwidth=6 midlayer7_minwidth=6 midlayer8_minwidth=10 midlayer8_prefwidth=10 bottomlayer_prefwidth=4 substack1={9319A519-0D26-40B3-8AF8-C4998BECF1C7} minimp=50.000000 maximp=50.000000 favimp=50.000000
Width POWER [InNetClass('PWR')] p2: maxlimit=100 minlimit=4 preferedwidth=10 toplayer_maxwidth=50 bottomlayer_maxwidth=50 substack1={9319A519-0D26-40B3-8AF8-C4998BECF1C7} toplayer_{9319a519-0d26-40b3-8af8-c4998becf1c7}_minwidth=1 toplayer_{9319a519-0d26-40b3-8af8-c4998becf1c7}_maxwidth=10 midlayer2_{9319a519-0d26-40b3-8af8-c4998becf1c7}_minwidth=1 midlayer2_{9319a519-0d26-40b3-8af8-c4998becf1c7}_maxwidth=10 midlayer3_{9319a519-0d26-40b3-8af8-c4998becf1c7}_minwidth=1 midlayer3_{9319a519-0d26-40b3-8af8-c4998becf1c7}_maxwidth=10 midlayer5_{9319a519-0d26-40b3-8af8-c4998becf1c7}_minwidth=1 midlayer5_{9319a519-0d26-40b3-8af8-c4998becf1c7}_maxwidth=10 midlayer6_{9319a519-0d26-40b3-8af8-c4998becf1c7}_minwidth=1 midlayer6_{9319a519-0d26-40b3-8af8-c4998becf1c7}_maxwidth=10 midlayer7_{9319a519-0d26-40b3-8af8-c4998becf1c7}_minwidth=1 midlayer7_{9319a519-0d26-40b3-8af8-c4998becf1c7}_maxwidth=10 midlayer8_{9319a519-0d26-40b3-8af8-c4998becf1c7}_minwidth=1 midlayer8_{9319a519-0d26-40b3-8af8-c4998becf1c7}_maxwidth=10 bottomlayer_{9319a519-0d26-40b3-8af8-c4998becf1c7}_minwidth=1 bottomlayer_{9319a519-0d26-40b3-8af8-c4998becf1c7}_maxwidth=10 minimp=50.000000 maximp=50.000000 favimp=50.000000 checkconnectedcopper=TRUE
Width [All] p3: maxlimit=100 minlimit=4 preferedwidth=10 toplayer_minwidth=6 toplayer_maxwidth=30 toplayer_prefwidth=8 midlayer2_minwidth=10 midlayer3_minwidth=10 midlayer5_minwidth=10 midlayer6_minwidth=6 midlayer6_maxwidth=30 midlayer6_prefwidth=6 midlayer7_minwidth=6 midlayer7_maxwidth=15 midlayer7_prefwidth=6 midlayer8_minwidth=10 bottomlayer_maxwidth=30 bottomlayer_prefwidth=8 substack1={9319A519-0D26-40B3-8AF8-C4998BECF1C7} minimp=50.000000 maximp=50.000000 favimp=50.000000 checkconnectedcopper=TRUE
12 further rules are at their usual default settings.

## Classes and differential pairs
component class "TRIPAD RESISTORS": C156 C162 R74 R96 R98 R100 R101 R103 R105 R121 R122 R178 R192 R196 R225 R230 R234 R237 R238 R239 R240 R260 R265 R270 R274 R325 R336 R338 R339 R390
component class PROC173A_PWR_Reference: R88 R95
component class "Room Definition1": U29
component class PROC196A_Auto_Ethernet_conn: C155 C156 C157 C161 C162 C166 C167 D15 D17 D18 D19 J4 L7 R260 R265 R270 R274 R275 R281 R282
differential pair class LVDS: LVDS_TX0 LVDS_TX1 LVDS_TX2_CLK LVDS_TX3_FRCLK
differential pair class Diff_120E: CAN_A CAN_B
differential pair class Diff_90E: FTDI_USBD XDSET_1_D
differential pair class Diff_100E: CSI2_0 CSI2_1 CSI2_CLK CSI2_RX0_0 CSI2_RX0_1 CSI2_RX0_CLK ETH_TD_1 ETH_TD_2 ETH_TD_3 ETH_TD_4 ETH_TRD LVDS_TX0 LVDS_TX1 LVDS_TX2_CLK LVDS_TX3_FRCLK TRD1 TRD2 TRD3 TX0 TX1 TX2 TX2_CLK TX3 TX3_FRCLK
net class RESET: AR_NRST AR_WRMRST
net class GPIO: BSS_UARTA_TX DSS_UARTA_RX DSS_UARTA_TX GPIO_3 GPIO_4 GPIO_8 GPIO_9 MSS_GPIO_1 MSS_GPIO_2 MSS_GPIO_11 MSS_GPIO_28 SOP1_MSS_SPIB_CS2 SOP3_MSS_GPIO_0 VPP_EN
net class EPWM: MSS_EPWMA0 MSS_EPWMB0
net class 40MHz_CLK: CLKP_SMA GND XTALM XTALP
net class MSS_SPIB: MSS_SPIB_CLK MSS_SPIB_CS0 MSS_SPIB_CS1 MSS_SPIB_MISO MSS_SPIB_MOSI
net class MSS_SPIA: MSS_SPIA_CLK MSS_SPIA_CS0 MSS_SPIA_MISO MSS_SPIA_MOSI
net class USB_DIFF: FTDI_USBD_N FTDI_USBD_P XDSET_1_D_N XDSET_1_D_P
net class CAN_DIFF: CANA_N CANA_P CANB_N CANB_P
component class PROC196A_3V3_Supply_Reference: C10 C21 C22 C23 C25 C26 C29 C118 C173 C195 L6 R1 R2 R4 R6 R7 R8 R9 R10 U2
net class RGMII_TX_RX: MSS_RGMII_RCLK MSS_RGMII_RCTL MSS_RGMII_RD0 MSS_RGMII_RD1 MSS_RGMII_RD2 MSS_RGMII_RD3 MSS_RGMII_TCLK MSS_RGMII_TCTL MSS_RGMII_TD0 MSS_RGMII_TD1 MSS_RGMII_TD2 MSS_RGMII_TD3 RGMII_RD0 RGMII_RD1 RGMII_RD2 RGMII_RD3 RGMII_TCLK RGMII_TD0 RGMII_TD1 RGMII_TD2 RGMII_TD3 RX_CLK RX_CTRL TX_CTRL
component class PROC196A_VPP_LDO: C145 C149 P1 R159 R409 U27
net class UART: MSS_RS232RX MSS_RS232TX MSS_UARTA_RX SOP4_MSS_UARTA_TX
net class PWR: 1V0 1V0_ETH 1V2 1V8 2V5_ETH 3V3 ERTH_GND FTDI_3V3 FTDI_VBUS FTDI_VCORE GND MIPI_VREF_DEBUG NetC1_2 NetC11_2 NetC13_2 NetC16_2 NetC24_2 NetC34_2 NetC97_1 NetC104_1 NetC149_2 NetJ8_1 NetJ8_5 NetJ9_1 NetJ9_2 NetJ10_1 VBAT_INT VDDC_1 VDDIO_ETH VLDO_3V3 VPP_1P7 XDSET_1_VBUS XDSET_VBAT XDSET_VREFA
net class MDIO: MSS_MDIO_CLK MSS_MDIO_DATA
net class I2C: MSS_I2CA_SCL MSS_I2CA_SDA
net class XDS_USB: XDSET_1_D_N XDSET_1_D_P XDSET_1_ID
net class TRACE: MIPI_DBG_DETECT
net class RGMII: ETH_TRD_N ETH_TRD_P NetR74_2 NetR230_2 NetR234_2 RGMII_RD0 RGMII_RD1 RGMII_RD2 RGMII_RD3 RGMII_TCLK RGMII_TD0 RGMII_TD1 RGMII_TD2 RGMII_TD3 RX_CLK RX_CTRL TD_1_N TD_1_P TD_2_N TD_2_P TD_3_N TD_3_P TD_4_N TD_4_P TX_CTRL
net class QSPI: QSPI_CS QSPI_D0 QSPI_D0_FLASH QSPI_D1 QSPI_D1_FLASH QSPI_D2 QSPI_D2_FLASH QSPI_D3 QSPI_D3_FLASH QSPI_SCLK QSPI_SCLK_FLASH
net class LVDS: LVDS_TX0_N LVDS_TX0_P LVDS_TX1_N LVDS_TX1_P LVDS_TX2_CLK_N LVDS_TX2_CLK_P LVDS_TX3_FRCLK_N LVDS_TX3_FRCLK_P TX0_N TX0_P TX1_N TX1_P TX2_CLK_N TX2_CLK_P TX2_N TX2_P TX3_FRCLK_N TX3_FRCLK_P TX3_N TX3_P
net class JTAG: DBG_SPI_CLK DBG_SPI_CS0 DBG_SPI_MISO DBG_SPI_MOSI EMU_TCK EMU_TDI EMU_TDO EMU_TMS MIPI_RTCK MSS_SPIB_CLK MSS_SPIB_CS0 MSS_SPIB_MISO MSS_SPIB_MOSI NetR188_1 NetR223_1 NetR353_2 NetR354_2 NetR355_2 NetR356_2 NetR357_2 NetR358_2 NetR359_2 NetR360_2 NetR377_2 NetR386_2 NetR399_1 PMIC_SPI_CLK PMIC_SPI_CS0 PMIC_SPI_MISO PMIC_SPI_MOSI SOP0_TDO TCK TDI TMS XDS_TCK XDS_TDI XDS_TDO XDS_TMS
net class CSI: CSI2_RX0_0_N CSI2_RX0_0_P CSI2_RX0_1_N CSI2_RX0_1_P CSI2_RX0_CLK_N CSI2_RX0_CLK_P
net class GPADC: DBG_GPADC1 DBG_GPADC2 DBG_GPADC3 DBG_GPADC5 DBG_GPADC6 GND GPADC1 GPADC2 GPADC3 GPADC5 GPADC6
net class FTDI_USB: FTDI_USBD_N FTDI_USBD_P FTDI_USBID
net class CLKOUT: DBG_EPWMA0 DBG_SPI_MISO DBG_XREF_CLK0 MCU_CLKOUT MSS_EPWMA0 MSS_SPIA_HOSTIRQ NetJ7_10 NetJ7_16 XREF_CLK0
net class CAN: CANA_N CANA_P CANA_STB CANB_N CANB_NSTB CANB_P MSS_MCANA_RX MSS_MCANA_TX MSS_MCANB_RX MSS_MCANB_TX NetC13_2 NetC24_2 NetR11_2 NetR12_2 NetR21_2 NetR25_2
component class "PROC196A_XDS110 Interface_1B": C49 C63 C66 C67 C70 C71 C109 R123 R124 R126 R127 R128 R129 R134 R136 R140 R152 R154 R155 R194 R284 R285 R387 R388 R389 U6 U7 Y2
component class "PROC196A_XDS110 Interface_1A": C41 C42 C43 C45 C50 C61 C62 C64 C74 C75 C76 J8 R161 R174 R175 U10
component class PROC196A_IO_Reference: C47 C106 C108 C131 C135 C136 J13 J14 J21 J22 J23 R3 R22 R23 R31 R88 R90 R95 R107 R109 R133 R156 R165 R172 R212 R213 R214 R216 R217 R218 R219 R220 R221 R224 R227 R228 R229 R231 R232 R233 R235 R236 R269 R271 R272 R273 R276 R277 R278 R279 R280 R315 R316 R326 R380 R381 R386 R392 R416 R417 TP1 TP4 TP7 TP9 U28 U29 Y3
component class PROC196A_Decoupling_Reference: C5 C92 C96 C102 C103 C107 C110 C111 C112 C113 C114 C115 C116 C117 C137 C138 C139 C140 C141 C142 C146 C150 C163 C164 C165 C168 C170 C172 C174 C175 C176 C177 C180 C181
component class PROC196A_Temp_Sensor: C133 R222 R317 R318 R319 U24
component class PROC196A_SOP_Reference: J17 J18 J20 R297 R298 R299 R300 R301 R302 R303 R304 R305 R306 R307 R308 R309 R310 R311 R312 R313
component class PROC196A_QSPI_Flash_Reference: C1 C2 R37 R38 R39 R40 R41 R42 R43 R44 R45 R49 U1
component class PROC196A_PWR_RST_LED: C99 C100 C101 C104 C105 C126 D2 D3 D4 D5 D6 D9 D11 D12 D13 D16 DS2 J12 L5 Q1 R36 R261 R262 R263 R264 R266 R267 R268 R331 R332 R333 R334 R335 R347 R362 SW1 SW2
component class PROC196A_PMIC_Reference: C3 C4 C6 C7 C8 C9 C15 C31 C58 C119 C120 C123 C124 C125 C127 C129 C130 C132 C134 C143 C144 C151 C152 C153 C169 C194 C198 C199 C200 C201 C202 J1 J5 J16 L1 L2 L8 L9 L10 NT1 NT2 NT3 NT4 R5 R13 R14 R17 R20 R61 R63 R67 R70 R71 R73 R75 R76 R99 R102 R104 R106 R111 R116 R125 R167 R176 R185 R186 R190 R193 R199 R200 R210 R291 R292 TP8 U8
component class PROC196A_JTAG_EMU_Connector: C98 J19 R72 R135 R138 R168 R189 R191 R192 R196 R226 R243 R244 R296 R321 R353 R354 R355 R356 R357 R358 R359 R360 R374 R375 R376 R503 R508 R512 S1 U23
component class PROC196A_Auto_Ethernet_PHY: C32 C35 C36 C37 C40 C44 C46 C51 C52 C54 C55 C95 C121 C122 C147 C148 C154 C171 C178 C182 C196 C197 D10 D14 FB1 FB2 R28 R34 R46 R48 R50 R51 R74 R77 R79 R89 R93 R96 R100 R178 R225 R230 R234 R237 R238 R239 R240 R242 R245 R246 R247 R248 R249 R250 R251 R252 R253 R254 R255 R256 R257 R258 R259 R314 R350 R367 TP2 TP3 U4 U33 Y5
component class PROC196A_FTDI: C68 C69 C72 C73 C77 C78 C79 C82 C83 C84 C86 C87 C88 C89 C90 C91 D1 L3 L4 R131 R144 R145 R146 R147 R148 R149 R150 R151 R153 R157 R158 R160 R162 R163 R164 R166 R169 R170 R171 R179 R180 R181 R184 R187 R201 R205 R330 U18 U19 Y1
component class PROC196A_FTDI_PWR: C39 C85 C93 C94 C97 J10 R182 R183 R202 R203 R204 R206 R207 R208 R209 U20 U21
component class PROC196A_Ethernet_PWR: C34 C38 C48 C53 C56 C57 C59 C60 C65 C158 C159 C160 C183 C184 C185 C186 C187 C188 C189 C190 C191 C192 C193 R293 R294 R295 U16 U17
component class PROC196A_Ethernet_PHY: C30 C33 D7 D8 R92 R97 R98 R101 R103 R105 R108 R112 R113 R117 R118 R120 R121 R122 R132 R137 R139 R141 R142 R143 R173 R195 R211 R286 R287 R288 R289 R290 R325 R336 R337 R338 R339 R340 R342 R344 R369 R370 R413 R414 TP5 U15 Y4
component class PROC196A_Ethernet_Magnetics: C27 C28 J9 R68 R69 R119 R130 R400 R401 R419 TP6 U13 U14
component class PROC196A_Debug_Connector: C18 J7 R80 R81 R82 R83 R84 R91 R94 R114 R115 R188 R197 R198 R215 R223 R283 R320 R322 R323 R324 R327 R328 R329 R341 R345 R349 R351 R361 R363 R364 R365 R366 R371 R377 R379 R390 R391 R399 R418 R422 R423 R424 R425 S2 U26
component class PROC196A_Current_Sensors: C14 C17 C19 C81 R26 R27 R29 R30 R32 R33 R35 R47 R56 R57 R58 R59 R60 R62 R64 R65 R66 R346 R348 R352 U9 U11 U12 U22
component class PROC196A_CAN_Interface: C11 C12 C13 C16 C20 C24 C80 C128 J2 J3 R11 R12 R15 R16 R18 R19 R21 R24 R25 R52 R53 R54 R55 R78 R85 R86 R87 R110 R177 SW3 U3 U5 U32
component class Header: J16 J17 J18 J20 J21 J22 J23 P1
component class Logo: Logo1
component class PROC196A_Hardware: "CAUTION HOT SURFACE1" "ESD Susceptible1" FID1 FID2 FID3 FID4 FID5 FID6 FID7 FID8 FID9 FID10 FID11 FID12 FID13 FID14 FID15 FID16 LBL1 Logo1 LOGO2 Logo3 Logo4 Logo5 ZZ1 ZZ2 ZZ3 ZZ4
component class FiducialMark: FID1 FID2 FID3 FID4 FID5 FID6 FID7 FID8 FID9 FID10 FID11 FID12 FID13 FID14 FID15 FID16
component class AssemblyNote: ZZ1 ZZ2 ZZ3 ZZ4
component class Label: LBL1
differential pair TX3: +TX3_P -TX3_N
differential pair TX3_FRCLK: +TX3_FRCLK_P -TX3_FRCLK_N
differential pair TX2: +TX2_P -TX2_N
